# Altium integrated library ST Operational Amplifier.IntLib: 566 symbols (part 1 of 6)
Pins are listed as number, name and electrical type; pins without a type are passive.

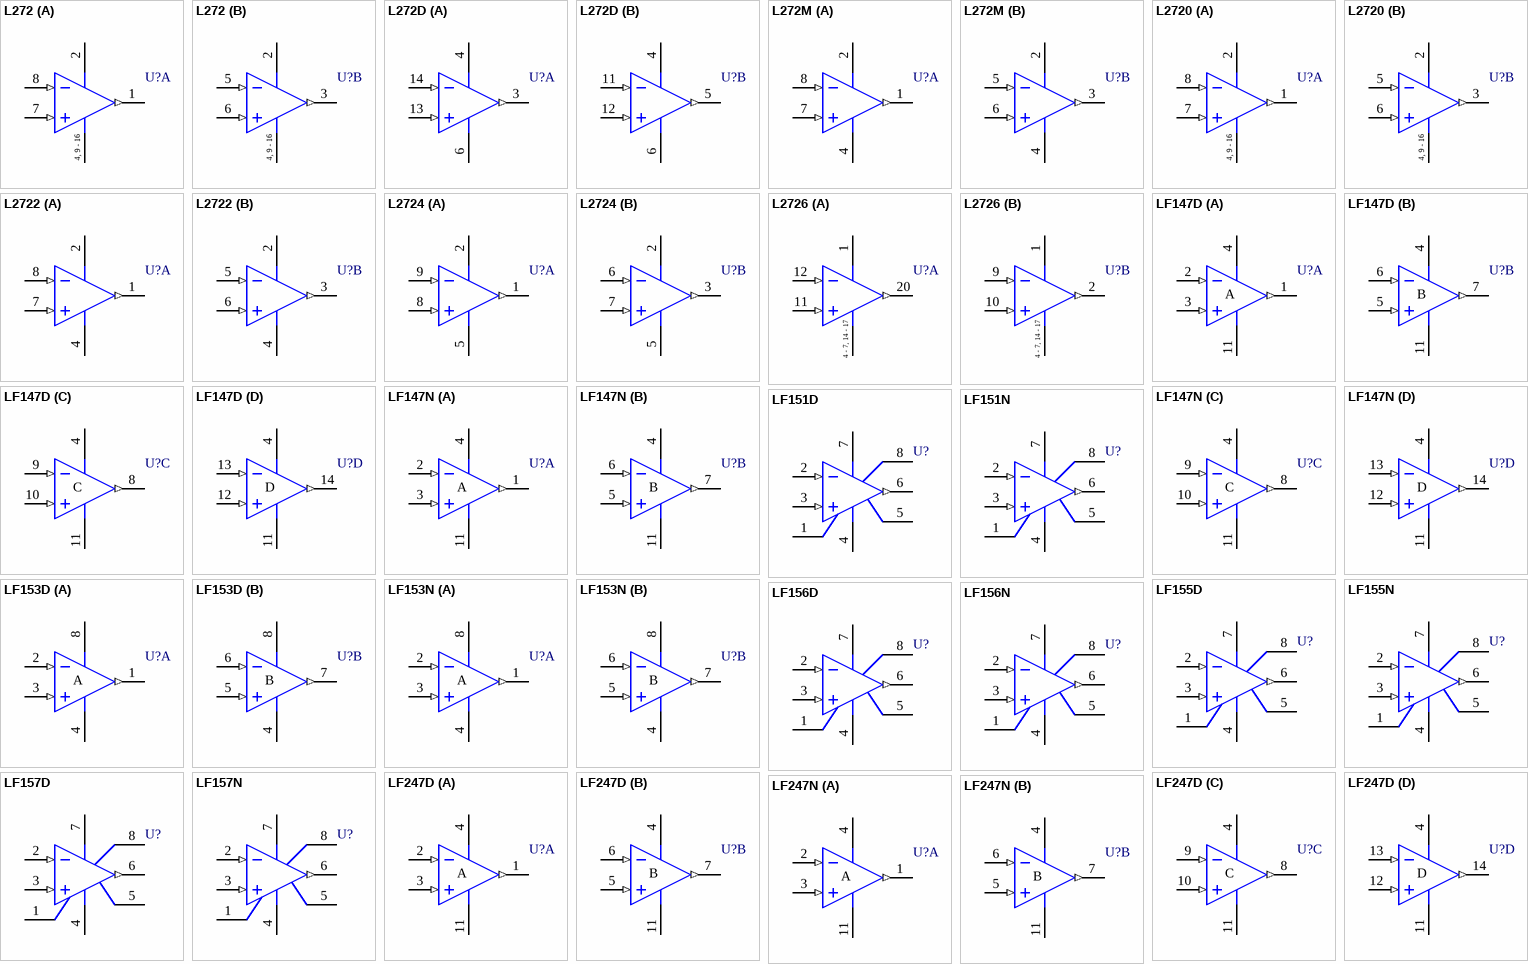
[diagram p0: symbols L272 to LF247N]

## L272
designator U?
Dual Power Operational Amplifier
footprint DIP16 (DIP; 16 Leads; Row Spacing 7.62 mm; Pitch 2.54 mm)
3D model DIP16 (DIP; 16 Leads; Row Spacing 7.62 mm; Pitch 2.54 mm)
pins on every part: 2 V+ (power), 4 V- (power), 9 V- (power), 10 V- (power), 11 V- (power), 12 V- (power), 13 V- (power), 14 V- (power), 15 V- (power), 16 V- (power)
part A pins: 1 OUT (out), 7 IN+ (in), 8 IN- (in)
part B pins: 3 OUT (out), 5 IN- (in), 6 IN+ (in)

## L272D
designator U?
Dual Power Operational Amplifier; Note: Pins 1, 2, 7, 8, 9, 10, 15 and 16 are NC and not drawn.
footprint SO16_N (SOIC, 16-Leads, Body 9.9x3.9mm, Pitch 1.27mm, IPC Medium Density)
footprint SO16_L (SOIC, 16-Leads, Body 9.9x3.9mm, Pitch 1.27mm, IPC High Density)
footprint SO16_M (SOIC, 16-Leads, Body 9.9x3.9mm, Pitch 1.27mm, IPC Low Density)
3D model SO16 (16-Pin Small Outline Integrated Circuit 1.27 mm Pitch)
pins on every part: 4 V+ (power), 6 V- (power)
part A pins: 3 OUT (out), 13 IN+ (in), 14 IN- (in)
part B pins: 5 OUT (out), 11 IN- (in), 12 IN+ (in)

## L272M
designator U?
Dual Power Operational Amplifier
footprint DIP8 (DIP; 8 Leads; Row Spacing 7.62 mm; Pitch 2.54 mm)
3D model DIP8 (DIP; 8 Leads; Row Spacing 7.62 mm; Pitch 2.54 mm)
pins on every part: 2 V+ (power), 4 V- (power)
part A pins: 1 OUT (out), 7 IN+ (in), 8 IN- (in)
part B pins: 3 OUT (out), 5 IN- (in), 6 IN+ (in)

## L2720
designator U?
Low-Drop Dual Power Operational Amplifier
footprint DIP16 (DIP; 16 Leads; Row Spacing 7.62 mm; Pitch 2.54 mm)
3D model DIP16 (DIP; 16 Leads; Row Spacing 7.62 mm; Pitch 2.54 mm)
pins on every part: 2 V+ (power), 4 V- (power), 9 V- (power), 10 V- (power), 11 V- (power), 12 V- (power), 13 V- (power), 14 V- (power), 15 V- (power), 16 V- (power)
part A pins: 1 OUT (out), 7 IN+ (in), 8 IN- (in)
part B pins: 3 OUT (out), 5 IN- (in), 6 IN+ (in)

## L2722
designator U?
Low-Drop Dual Power Operational Amplifier
footprint MDIP8 (DIP; 8 Leads; Row Spacing 7.62 mm; Pitch 2.54 mm)
pins on every part: 2 V+ (power), 4 V- (power)
part A pins: 1 OUT (out), 7 IN+ (in), 8 IN- (in)
part B pins: 3 OUT (out), 5 IN- (in), 6 IN+ (in)

## L2724
designator U?
Low-Drop Dual Power Operational Amplifier; Note: Pin number 4 is NC and not drawn.
footprint SIP9 (TO, Thru-Hole, Vertical, Heatsink Mounted; 9 In-Line Leads; Pitch 2.54 mm)
pins on every part: 2 V+ (power), 5 V- (power)
part A pins: 1 OUT (out), 8 IN+ (in), 9 IN- (in)
part B pins: 3 OUT (out), 6 IN- (in), 7 IN+ (in)

## L2726
designator U?
Low-Drop Dual Power Operational Amplifier; Note: Pins 3, 8, 13, 18  and 19 are NC and are not drawn.
footprint SO20_N (SOIC, 20-Leads, Body 12.8x7.5mm, Pitch 1.27mm, IPC Medium Density)
footprint SO20_L (SOIC, 20-Leads, Body 12.8x7.5mm, Pitch 1.27mm, IPC High Density)
footprint SO20_M (SOIC, 20-Leads, Body 12.8x7.5mm, Pitch 1.27mm, IPC Low Density)
3D model SO20 (20-Pin Plastic Small Outline Integrated Circuit 1.27 mm Pitch)
pins on every part: 1 V+ (power), 4 V- (power), 5 V- (power), 6 V- (power), 7 V- (power), 14 V- (power), 15 V- (power), 16 V- (power), 17 V- (power)
part A pins: 11 IN+ (in), 12 IN- (in), 20 OUT (out)
part B pins: 2 OUT (out), 9 IN- (in), 10 IN+ (in)

## LF147D
designator U?
Wide-Bandwidth Quad J-FET Operational Amplifier
footprint SO14_N (SOIC, 14-Leads, Body 8.7x3.9mm, Pitch 1.27mm, IPC Medium Density)
footprint SO14_L (SOIC, 14-Leads, Body 8.7x3.9mm, Pitch 1.27mm, IPC High Density)
footprint SO14_M (SOIC, 14-Leads, Body 8.7x3.9mm, Pitch 1.27mm, IPC Low Density)
3D model SO14 (14-Pin Small Outline Integrated Circuit 1.27 mm Pitch)
pins on every part: 4 V+ (power), 11 V- (power)
part A pins: 1 OUT (out), 2 IN- (in), 3 IN+ (in)
part B pins: 5 IN+ (in), 6 IN- (in), 7 OUT (out)
part C pins: 8 OUT (out), 9 IN- (in), 10 IN+ (in)
part D pins: 12 IN+ (in), 13 IN- (in), 14 OUT (out)

## LF147N
designator U?
Wide-Bandwidth Quad J-FET Operational Amplifier
footprint DIP14 (DIP; 14 Leads; Row Spacing 7.62 mm; Pitch 2.54 mm)
3D model DIP14 (DIP; 14 Leads; Row Spacing 7.62 mm; Pitch 2.54 mm)
pins on every part: 4 V+ (power), 11 V- (power)
part A pins: 1 OUT (out), 2 IN- (in), 3 IN+ (in)
part B pins: 5 IN+ (in), 6 IN- (in), 7 OUT (out)
part C pins: 8 OUT (out), 9 IN- (in), 10 IN+ (in)
part D pins: 12 IN+ (in), 13 IN- (in), 14 OUT (out)

## LF151D
designator U?
Wide-Bandwidth Single J-FET Operational Amplifier
footprint SO8_N (SOIC, 8-Leads, Body 4.9x3.9mm, Pitch 1.27mm, IPC Medium Density)
footprint SO8_L (SOIC, 8-Leads, Body 4.9x3.9mm, Pitch 1.27mm, IPC High Density)
footprint SO8_M (SOIC, 8-Leads, Body 4.9x3.9mm, Pitch 1.27mm, IPC Low Density)
3D model SO8 (8-Pin Small Outline Integrated Circuit 1.27 mm Pitch)
pins: 1 OS NULL, 2 IN- (in), 3 IN+ (in), 4 V- (power), 5 OS NULL, 6 OUT (out), 7 V+ (power), 8 NC

## LF151N
designator U?
Wide-Bandwidth Single J-FET Operational Amplifier
footprint DIP8 (DIP; 8 Leads; Row Spacing 7.62 mm; Pitch 2.54 mm)
3D model DIP8 (DIP; 8 Leads; Row Spacing 7.62 mm; Pitch 2.54 mm)
pins: 1 OS NULL, 2 IN- (in), 3 IN+ (in), 4 V- (power), 5 OS NULL, 6 OUT (out), 7 V+ (power), 8 NC

## LF153D
designator U?
Wide-Bandwidth Dual J-FET Operational Amplifier
footprint SO8_N (SOIC, 8-Leads, Body 4.9x3.9mm, Pitch 1.27mm, IPC Medium Density)
footprint SO8_L (SOIC, 8-Leads, Body 4.9x3.9mm, Pitch 1.27mm, IPC High Density)
footprint SO8_M (SOIC, 8-Leads, Body 4.9x3.9mm, Pitch 1.27mm, IPC Low Density)
3D model SO8 (8-Pin Small Outline Integrated Circuit 1.27 mm Pitch)
pins on every part: 4 V- (power), 8 V+ (power)
part A pins: 1 OUT (out), 2 IN- (in), 3 IN+ (in)
part B pins: 5 IN+ (in), 6 IN- (in), 7 OUT (out)

## LF153N
designator U?
Wide-Bandwidth Dual J-FET Operational Amplifier
footprint DIP8 (DIP; 8 Leads; Row Spacing 7.62 mm; Pitch 2.54 mm)
3D model DIP8 (DIP; 8 Leads; Row Spacing 7.62 mm; Pitch 2.54 mm)
pins on every part: 4 V- (power), 8 V+ (power)
part A pins: 1 OUT (out), 2 IN- (in), 3 IN+ (in)
part B pins: 5 IN+ (in), 6 IN- (in), 7 OUT (out)

## LF155D
designator U?
Wide-Bandwidth Single J-FET Operational Amplifier
footprint SOP8_N (SOIC, 8-Leads, Body 4.9x3.9mm, Pitch 1.27mm, IPC Medium Density)
footprint SOP8_L (SOIC, 8-Leads, Body 4.9x3.9mm, Pitch 1.27mm, IPC High Density)
footprint SOP8_M (SOIC, 8-Leads, Body 4.9x3.9mm, Pitch 1.27mm, IPC Low Density)
3D model SOP8 (8-Pin Small Outline Integrated Circuit 1.27 mm Pitch)
simulation model LF155 (SUBCKT)
pins: 1 OS NULL, 2 IN- (in), 3 IN+ (in), 4 V- (power), 5 OS NULL, 6 OUT (out), 7 V+ (power), 8 NC

## LF155N
designator U?
Wide-Bandwidth Single J-FET Operational Amplifier
footprint DIP8 (DIP; 8 Leads; Row Spacing 7.62 mm; Pitch 2.54 mm)
3D model DIP8 (DIP; 8 Leads; Row Spacing 7.62 mm; Pitch 2.54 mm)
simulation model LF155 (SUBCKT)
pins: 1 OS NULL, 2 IN- (in), 3 IN+ (in), 4 V- (power), 5 OS NULL, 6 OUT (out), 7 V+ (power), 8 NC

## LF156D
designator U?
Wide-Bandwidth Single J-FET Operational Amplifier
footprint SO8_N (SOIC, 8-Leads, Body 4.9x3.9mm, Pitch 1.27mm, IPC Medium Density)
footprint SO8_L (SOIC, 8-Leads, Body 4.9x3.9mm, Pitch 1.27mm, IPC High Density)
footprint SO8_M (SOIC, 8-Leads, Body 4.9x3.9mm, Pitch 1.27mm, IPC Low Density)
3D model SO8 (8-Pin Small Outline Integrated Circuit 1.27 mm Pitch)
simulation model LF156 (SUBCKT)
pins: 1 OS NULL, 2 IN- (in), 3 IN+ (in), 4 V- (power), 5 OS NULL, 6 OUT (out), 7 V+ (power), 8 NC

## LF156N
designator U?
Wide-Bandwidth Single J-FET Operational Amplifier
footprint DIP8 (DIP; 8 Leads; Row Spacing 7.62 mm; Pitch 2.54 mm)
3D model DIP8 (DIP; 8 Leads; Row Spacing 7.62 mm; Pitch 2.54 mm)
simulation model LF156 (SUBCKT)
pins: 1 OS NULL, 2 IN- (in), 3 IN+ (in), 4 V- (power), 5 OS NULL, 6 OUT (out), 7 V+ (power), 8 NC

## LF157D
designator U?
Wide-Bandwidth Single J-FET Operational Amplifier
footprint SO8_N (SOIC, 8-Leads, Body 4.9x3.9mm, Pitch 1.27mm, IPC Medium Density)
footprint SO8_L (SOIC, 8-Leads, Body 4.9x3.9mm, Pitch 1.27mm, IPC High Density)
footprint SO8_M (SOIC, 8-Leads, Body 4.9x3.9mm, Pitch 1.27mm, IPC Low Density)
3D model SO8 (8-Pin Small Outline Integrated Circuit 1.27 mm Pitch)
pins: 1 OS NULL, 2 IN- (in), 3 IN+ (in), 4 V- (power), 5 OS NULL, 6 OUT (out), 7 V+ (power), 8 NC

## LF157N
designator U?
Wide-Bandwidth Single J-FET Operational Amplifier
footprint DIP8 (DIP; 8 Leads; Row Spacing 7.62 mm; Pitch 2.54 mm)
3D model DIP8 (DIP; 8 Leads; Row Spacing 7.62 mm; Pitch 2.54 mm)
pins: 1 OS NULL, 2 IN- (in), 3 IN+ (in), 4 V- (power), 5 OS NULL, 6 OUT (out), 7 V+ (power), 8 NC

## LF247D
designator U?
Wide-Bandwidth Quad J-FET Operational Amplifier
footprint SO14_N (SOIC, 14-Leads, Body 8.7x3.9mm, Pitch 1.27mm, IPC Medium Density)
footprint SO14_L (SOIC, 14-Leads, Body 8.7x3.9mm, Pitch 1.27mm, IPC High Density)
footprint SO14_M (SOIC, 14-Leads, Body 8.7x3.9mm, Pitch 1.27mm, IPC Low Density)
3D model SO14 (14-Pin Small Outline Integrated Circuit 1.27 mm Pitch)
pins on every part: 4 V+ (power), 11 V- (power)
part A pins: 1 OUT (out), 2 IN- (in), 3 IN+ (in)
part B pins: 5 IN+ (in), 6 IN- (in), 7 OUT (out)
part C pins: 8 OUT (out), 9 IN- (in), 10 IN+ (in)
part D pins: 12 IN+ (in), 13 IN- (in), 14 OUT (out)

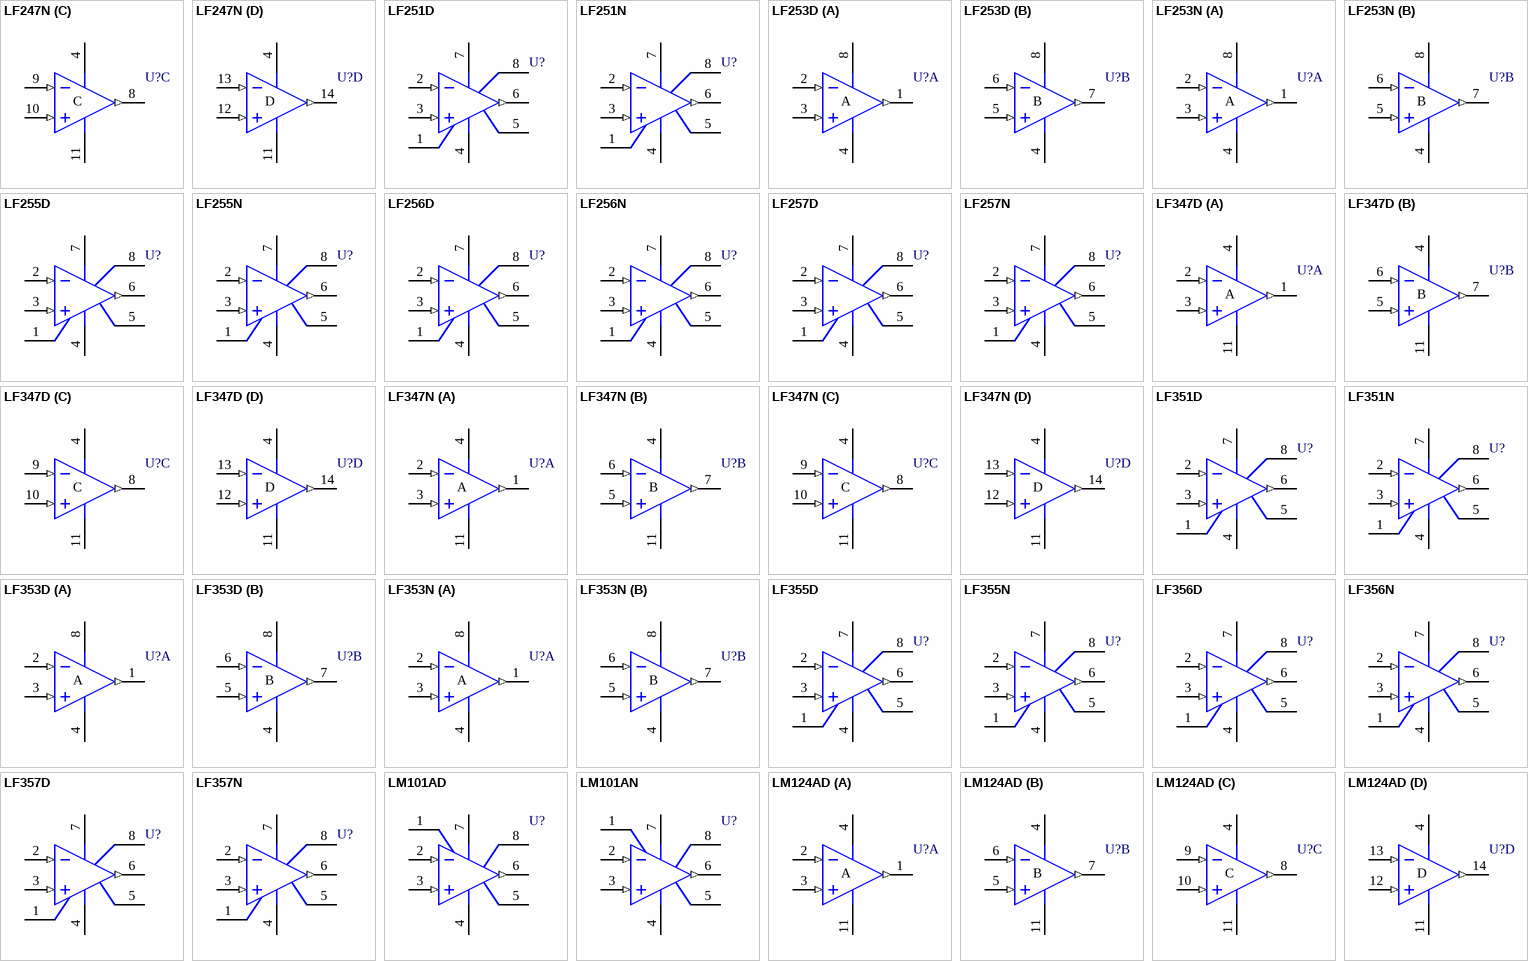
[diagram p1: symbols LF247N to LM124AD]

## LF247N
designator U?
Wide-Bandwidth Quad J-FET Operational Amplifier
footprint DIP14 (DIP; 14 Leads; Row Spacing 7.62 mm; Pitch 2.54 mm)
3D model DIP14 (DIP; 14 Leads; Row Spacing 7.62 mm; Pitch 2.54 mm)
pins on every part: 4 V+ (power), 11 V- (power)
part A pins: 1 OUT (out), 2 IN- (in), 3 IN+ (in)
part B pins: 5 IN+ (in), 6 IN- (in), 7 OUT (out)
part C pins: 8 OUT (out), 9 IN- (in), 10 IN+ (in)
part D pins: 12 IN+ (in), 13 IN- (in), 14 OUT (out)

## LF251D
designator U?
Wide-Bandwidth Single J-FET Operational Amplifier
footprint SO8_N (SOIC, 8-Leads, Body 4.9x3.9mm, Pitch 1.27mm, IPC Medium Density)
footprint SO8_L (SOIC, 8-Leads, Body 4.9x3.9mm, Pitch 1.27mm, IPC High Density)
footprint SO8_M (SOIC, 8-Leads, Body 4.9x3.9mm, Pitch 1.27mm, IPC Low Density)
3D model SO8 (8-Pin Small Outline Integrated Circuit 1.27 mm Pitch)
pins: 1 OS NULL, 2 IN- (in), 3 IN+ (in), 4 V- (power), 5 OS NULL, 6 OUT (out), 7 V+ (power), 8 NC

## LF251N
designator U?
Wide-Bandwidth Single J-FET Operational Amplifier
footprint DIP8 (DIP; 8 Leads; Row Spacing 7.62 mm; Pitch 2.54 mm)
3D model DIP8 (DIP; 8 Leads; Row Spacing 7.62 mm; Pitch 2.54 mm)
pins: 1 OS NULL, 2 IN- (in), 3 IN+ (in), 4 V- (power), 5 OS NULL, 6 OUT (out), 7 V+ (power), 8 NC

## LF253D
designator U?
Wide-Bandwidth Dual J-FET Operational Amplifier
footprint SO8_N (SOIC, 8-Leads, Body 4.9x3.9mm, Pitch 1.27mm, IPC Medium Density)
footprint SO8_L (SOIC, 8-Leads, Body 4.9x3.9mm, Pitch 1.27mm, IPC High Density)
footprint SO8_M (SOIC, 8-Leads, Body 4.9x3.9mm, Pitch 1.27mm, IPC Low Density)
3D model SO8 (8-Pin Small Outline Integrated Circuit 1.27 mm Pitch)
pins on every part: 4 V- (power), 8 V+ (power)
part A pins: 1 OUT (out), 2 IN- (in), 3 IN+ (in)
part B pins: 5 IN+ (in), 6 IN- (in), 7 OUT (out)

## LF253N
designator U?
Wide-Bandwidth Dual J-FET Operational Amplifier
footprint DIP8 (DIP; 8 Leads; Row Spacing 7.62 mm; Pitch 2.54 mm)
3D model DIP8 (DIP; 8 Leads; Row Spacing 7.62 mm; Pitch 2.54 mm)
pins on every part: 4 V- (power), 8 V+ (power)
part A pins: 1 OUT (out), 2 IN- (in), 3 IN+ (in)
part B pins: 5 IN+ (in), 6 IN- (in), 7 OUT (out)

## LF255D
designator U?
Wide-Bandwidth Single J-FET Operational Amplifier
footprint SO8_N (SOIC, 8-Leads, Body 4.9x3.9mm, Pitch 1.27mm, IPC Medium Density)
footprint SO8_L (SOIC, 8-Leads, Body 4.9x3.9mm, Pitch 1.27mm, IPC High Density)
footprint SO8_M (SOIC, 8-Leads, Body 4.9x3.9mm, Pitch 1.27mm, IPC Low Density)
3D model SO8 (8-Pin Small Outline Integrated Circuit 1.27 mm Pitch)
pins: 1 OS NULL, 2 IN- (in), 3 IN+ (in), 4 V- (power), 5 OS NULL, 6 OUT (out), 7 V+ (power), 8 NC

## LF255N
designator U?
Wide-Bandwidth Single J-FET Operational Amplifier
footprint DIP8 (DIP; 8 Leads; Row Spacing 7.62 mm; Pitch 2.54 mm)
3D model DIP8 (DIP; 8 Leads; Row Spacing 7.62 mm; Pitch 2.54 mm)
pins: 1 OS NULL, 2 IN- (in), 3 IN+ (in), 4 V- (power), 5 OS NULL, 6 OUT (out), 7 V+ (power), 8 NC

## LF256D
designator U?
Wide-Bandwidth Single J-FET Operational Amplifier
footprint SO8_N (SOIC, 8-Leads, Body 4.9x3.9mm, Pitch 1.27mm, IPC Medium Density)
footprint SO8_L (SOIC, 8-Leads, Body 4.9x3.9mm, Pitch 1.27mm, IPC High Density)
footprint SO8_M (SOIC, 8-Leads, Body 4.9x3.9mm, Pitch 1.27mm, IPC Low Density)
3D model SO8 (8-Pin Small Outline Integrated Circuit 1.27 mm Pitch)
pins: 1 OS NULL, 2 IN- (in), 3 IN+ (in), 4 V- (power), 5 OS NULL, 6 OUT (out), 7 V+ (power), 8 NC

## LF256N
designator U?
Wide-Bandwidth Single J-FET Operational Amplifier
footprint DIP8 (DIP; 8 Leads; Row Spacing 7.62 mm; Pitch 2.54 mm)
3D model DIP8 (DIP; 8 Leads; Row Spacing 7.62 mm; Pitch 2.54 mm)
pins: 1 OS NULL, 2 IN- (in), 3 IN+ (in), 4 V- (power), 5 OS NULL, 6 OUT (out), 7 V+ (power), 8 NC

## LF257D
designator U?
Wide-Bandwidth Single J-FET Operational Amplifier
footprint SO8_N (SOIC, 8-Leads, Body 4.9x3.9mm, Pitch 1.27mm, IPC Medium Density)
footprint SO8_L (SOIC, 8-Leads, Body 4.9x3.9mm, Pitch 1.27mm, IPC High Density)
footprint SO8_M (SOIC, 8-Leads, Body 4.9x3.9mm, Pitch 1.27mm, IPC Low Density)
3D model SO8 (8-Pin Small Outline Integrated Circuit 1.27 mm Pitch)
pins: 1 OS NULL, 2 IN- (in), 3 IN+ (in), 4 V- (power), 5 OS NULL, 6 OUT (out), 7 V+ (power), 8 NC

## LF257N
designator U?
Wide-Bandwidth Single J-FET Operational Amplifier
footprint DIP8 (DIP; 8 Leads; Row Spacing 7.62 mm; Pitch 2.54 mm)
3D model DIP8 (DIP; 8 Leads; Row Spacing 7.62 mm; Pitch 2.54 mm)
pins: 1 OS NULL, 2 IN- (in), 3 IN+ (in), 4 V- (power), 5 OS NULL, 6 OUT (out), 7 V+ (power), 8 NC

## LF347D
designator U?
Wide-Bandwidth Quad J-FET Operational Amplifier
footprint SO14_N (SOIC, 14-Leads, Body 8.7x3.9mm, Pitch 1.27mm, IPC Medium Density)
footprint SO14_L (SOIC, 14-Leads, Body 8.7x3.9mm, Pitch 1.27mm, IPC High Density)
footprint SO14_M (SOIC, 14-Leads, Body 8.7x3.9mm, Pitch 1.27mm, IPC Low Density)
3D model SO14 (14-Pin Small Outline Integrated Circuit 1.27 mm Pitch)
simulation model LF347 (SUBCKT)
pins on every part: 4 V+ (power), 11 V- (power)
part A pins: 1 OUT (out), 2 IN- (in), 3 IN+ (in)
part B pins: 5 IN+ (in), 6 IN- (in), 7 OUT (out)
part C pins: 8 OUT (out), 9 IN- (in), 10 IN+ (in)
part D pins: 12 IN+ (in), 13 IN- (in), 14 OUT (out)

## LF347N
designator U?
Wide-Bandwidth Quad J-FET Operational Amplifier
footprint DIP14 (DIP; 14 Leads; Row Spacing 7.62 mm; Pitch 2.54 mm)
3D model DIP14 (DIP; 14 Leads; Row Spacing 7.62 mm; Pitch 2.54 mm)
simulation model LF347 (SUBCKT)
pins on every part: 4 V+ (power), 11 V- (power)
part A pins: 1 OUT (out), 2 IN- (in), 3 IN+ (in)
part B pins: 5 IN+ (in), 6 IN- (in), 7 OUT (out)
part C pins: 8 OUT (out), 9 IN- (in), 10 IN+ (in)
part D pins: 12 IN+ (in), 13 IN- (in), 14 OUT (out)

## LF351D
designator U?
Wide-Bandwidth Single J-FET Operational Amplifier
footprint SO8_N (SOIC, 8-Leads, Body 4.9x3.9mm, Pitch 1.27mm, IPC Medium Density)
footprint SO8_L (SOIC, 8-Leads, Body 4.9x3.9mm, Pitch 1.27mm, IPC High Density)
footprint SO8_M (SOIC, 8-Leads, Body 4.9x3.9mm, Pitch 1.27mm, IPC Low Density)
3D model SO8 (8-Pin Small Outline Integrated Circuit 1.27 mm Pitch)
simulation model LF351 (SUBCKT)
pins: 1 OS NULL, 2 IN- (in), 3 IN+ (in), 4 V- (power), 5 OS NULL, 6 OUT (out), 7 V+ (power), 8 NC

## LF351N
designator U?
Wide-Bandwidth Single J-FET Operational Amplifier
footprint DIP8 (DIP; 8 Leads; Row Spacing 7.62 mm; Pitch 2.54 mm)
3D model DIP8 (DIP; 8 Leads; Row Spacing 7.62 mm; Pitch 2.54 mm)
simulation model LF351 (SUBCKT)
pins: 1 OS NULL, 2 IN- (in), 3 IN+ (in), 4 V- (power), 5 OS NULL, 6 OUT (out), 7 V+ (power), 8 NC

## LF353D
designator U?
Wide-Bandwidth Dual J-FET Operational Amplifier
footprint SO8_N (SOIC, 8-Leads, Body 4.9x3.9mm, Pitch 1.27mm, IPC Medium Density)
footprint SO8_L (SOIC, 8-Leads, Body 4.9x3.9mm, Pitch 1.27mm, IPC High Density)
footprint SO8_M (SOIC, 8-Leads, Body 4.9x3.9mm, Pitch 1.27mm, IPC Low Density)
3D model SO8 (8-Pin Small Outline Integrated Circuit 1.27 mm Pitch)
simulation model LF353D (SUBCKT)
pins on every part: 4 V- (power), 8 V+ (power)
part A pins: 1 OUT (out), 2 IN- (in), 3 IN+ (in)
part B pins: 5 IN+ (in), 6 IN- (in), 7 OUT (out)

## LF353N
designator U?
Wide-Bandwidth Dual J-FET Operational Amplifier
footprint DIP8 (DIP; 8 Leads; Row Spacing 7.62 mm; Pitch 2.54 mm)
3D model DIP8 (DIP; 8 Leads; Row Spacing 7.62 mm; Pitch 2.54 mm)
simulation model LF353N (SUBCKT)
pins on every part: 4 V- (power), 8 V+ (power)
part A pins: 1 OUT (out), 2 IN- (in), 3 IN+ (in)
part B pins: 5 IN+ (in), 6 IN- (in), 7 OUT (out)

## LF355D
designator U?
Wide-Bandwidth Single J-FET Operational Amplifier
footprint SO8_N (SOIC, 8-Leads, Body 4.9x3.9mm, Pitch 1.27mm, IPC Medium Density)
footprint SO8_L (SOIC, 8-Leads, Body 4.9x3.9mm, Pitch 1.27mm, IPC High Density)
footprint SO8_M (SOIC, 8-Leads, Body 4.9x3.9mm, Pitch 1.27mm, IPC Low Density)
3D model SO8 (8-Pin Small Outline Integrated Circuit 1.27 mm Pitch)
simulation model LF355 (SUBCKT)
pins: 1 OS NULL, 2 IN- (in), 3 IN+ (in), 4 V- (power), 5 OS NULL, 6 OUT (out), 7 V+ (power), 8 NC

## LF355N
designator U?
Wide-Bandwidth Single J-FET Operational Amplifier
footprint DIP8 (DIP; 8 Leads; Row Spacing 7.62 mm; Pitch 2.54 mm)
3D model DIP8 (DIP; 8 Leads; Row Spacing 7.62 mm; Pitch 2.54 mm)
simulation model LF355 (SUBCKT)
pins: 1 OS NULL, 2 IN- (in), 3 IN+ (in), 4 V- (power), 5 OS NULL, 6 OUT (out), 7 V+ (power), 8 NC

## LF356D
designator U?
Wide-Bandwidth Single J-FET Operational Amplifier
footprint SO8_N (SOIC, 8-Leads, Body 4.9x3.9mm, Pitch 1.27mm, IPC Medium Density)
footprint SO8_L (SOIC, 8-Leads, Body 4.9x3.9mm, Pitch 1.27mm, IPC High Density)
footprint SO8_M (SOIC, 8-Leads, Body 4.9x3.9mm, Pitch 1.27mm, IPC Low Density)
3D model SO8 (8-Pin Small Outline Integrated Circuit 1.27 mm Pitch)
simulation model LF356 (SUBCKT)
pins: 1 OS NULL, 2 IN- (in), 3 IN+ (in), 4 V- (power), 5 OS NULL, 6 OUT (out), 7 V+ (power), 8 NC

## LF356N
designator U?
Wide-Bandwidth Single J-FET Operational Amplifier
footprint DIP8 (DIP; 8 Leads; Row Spacing 7.62 mm; Pitch 2.54 mm)
3D model DIP8 (DIP; 8 Leads; Row Spacing 7.62 mm; Pitch 2.54 mm)
simulation model LF356 (SUBCKT)
pins: 1 OS NULL, 2 IN- (in), 3 IN+ (in), 4 V- (power), 5 OS NULL, 6 OUT (out), 7 V+ (power), 8 NC

## LF357D
designator U?
Wide-Bandwidth Single J-FET Operational Amplifier
footprint SO8_N (SOIC, 8-Leads, Body 4.9x3.9mm, Pitch 1.27mm, IPC Medium Density)
footprint SO8_L (SOIC, 8-Leads, Body 4.9x3.9mm, Pitch 1.27mm, IPC High Density)
footprint SO8_M (SOIC, 8-Leads, Body 4.9x3.9mm, Pitch 1.27mm, IPC Low Density)
3D model SO8 (8-Pin Small Outline Integrated Circuit 1.27 mm Pitch)
pins: 1 OS NULL, 2 IN- (in), 3 IN+ (in), 4 V- (power), 5 OS NULL, 6 OUT (out), 7 V+ (power), 8 NC

## LF357N
designator U?
Wide-Bandwidth Single J-FET Operational Amplifier
footprint DIP8 (DIP; 8 Leads; Row Spacing 7.62 mm; Pitch 2.54 mm)
3D model DIP8 (DIP; 8 Leads; Row Spacing 7.62 mm; Pitch 2.54 mm)
pins: 1 OS NULL, 2 IN- (in), 3 IN+ (in), 4 V- (power), 5 OS NULL, 6 OUT (out), 7 V+ (power), 8 NC

## LM101AD
designator U?
Single Operational Amplifier
footprint SO8_N (SOIC, 8-Leads, Body 4.9x3.9mm, Pitch 1.27mm, IPC Medium Density)
footprint SO8_L (SOIC, 8-Leads, Body 4.9x3.9mm, Pitch 1.27mm, IPC High Density)
footprint SO8_M (SOIC, 8-Leads, Body 4.9x3.9mm, Pitch 1.27mm, IPC Low Density)
3D model SO8 (8-Pin Small Outline Integrated Circuit 1.27 mm Pitch)
simulation model LM101A (SUBCKT)
pins: 1 BAL/CMPEN1, 2 IN- (in), 3 IN+ (in), 4 V- (power), 5 BAL, 6 OUT (out), 7 V+ (power), 8 CMPEN2

## LM101AN
designator U?
Single Operational Amplifier
footprint DIP8 (DIP; 8 Leads; Row Spacing 7.62 mm; Pitch 2.54 mm)
3D model DIP8 (DIP; 8 Leads; Row Spacing 7.62 mm; Pitch 2.54 mm)
simulation model LM101A (SUBCKT)
pins: 1 BAL/CMPEN1, 2 IN- (in), 3 IN+ (in), 4 V- (power), 5 BAL, 6 OUT (out), 7 V+ (power), 8 CMPEN2

## LM124AD
designator U?
Low-Power Quad Operational Amplifier
footprint SO14_N (SOIC, 14-Leads, Body 8.7x3.9mm, Pitch 1.27mm, IPC Medium Density)
footprint SO14_L (SOIC, 14-Leads, Body 8.7x3.9mm, Pitch 1.27mm, IPC High Density)
footprint SO14_M (SOIC, 14-Leads, Body 8.7x3.9mm, Pitch 1.27mm, IPC Low Density)
3D model SO14 (14-Pin Small Outline Integrated Circuit 1.27 mm Pitch)
pins on every part: 4 V+ (power), 11 V- (power)
part A pins: 1 OUT (out), 2 IN- (in), 3 IN+ (in)
part B pins: 5 IN+ (in), 6 IN- (in), 7 OUT (out)
part C pins: 8 OUT (out), 9 IN- (in), 10 IN+ (in)
part D pins: 12 IN+ (in), 13 IN- (in), 14 OUT (out)

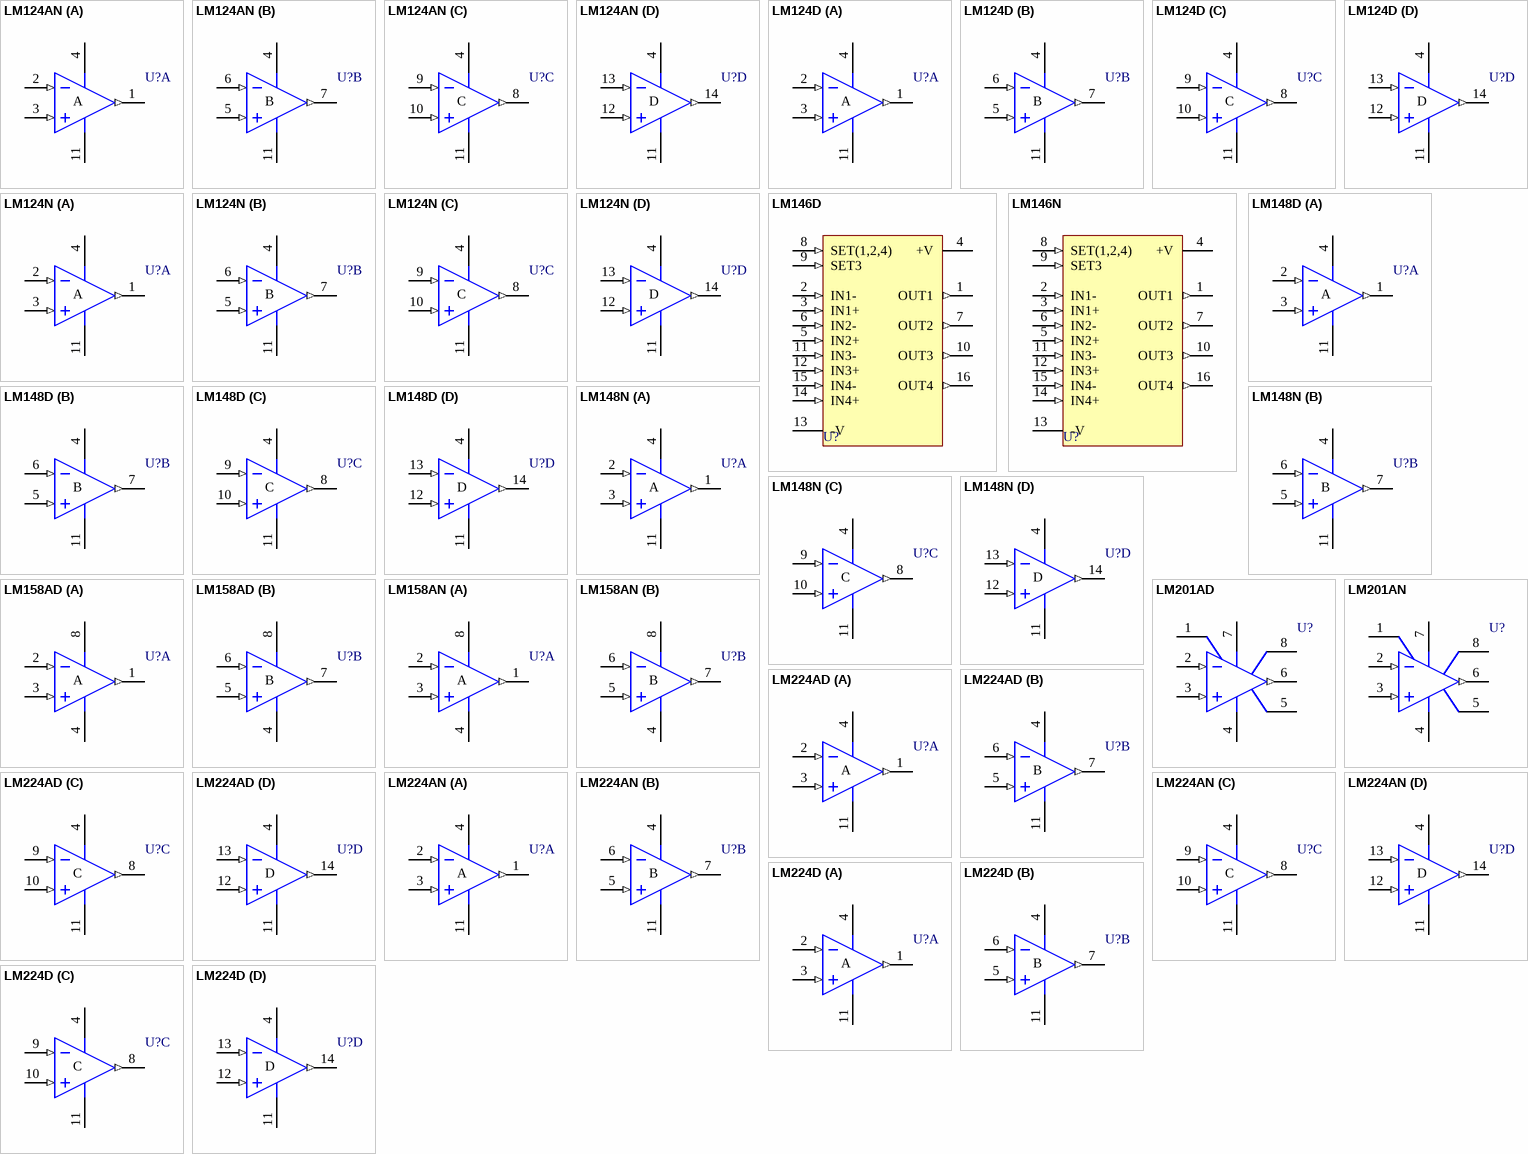
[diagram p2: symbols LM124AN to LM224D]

## LM124AN
designator U?
Low-Power Quad Operational Amplifier
footprint DIP14 (DIP; 14 Leads; Row Spacing 7.62 mm; Pitch 2.54 mm)
3D model DIP14 (DIP; 14 Leads; Row Spacing 7.62 mm; Pitch 2.54 mm)
pins on every part: 4 V+ (power), 11 V- (power)
part A pins: 1 OUT (out), 2 IN- (in), 3 IN+ (in)
part B pins: 5 IN+ (in), 6 IN- (in), 7 OUT (out)
part C pins: 8 OUT (out), 9 IN- (in), 10 IN+ (in)
part D pins: 12 IN+ (in), 13 IN- (in), 14 OUT (out)

## LM124D
designator U?
Low-Power Quad Operational Amplifier
footprint SO14_N (SOIC, 14-Leads, Body 8.7x3.9mm, Pitch 1.27mm, IPC Medium Density)
footprint SO14_L (SOIC, 14-Leads, Body 8.7x3.9mm, Pitch 1.27mm, IPC High Density)
footprint SO14_M (SOIC, 14-Leads, Body 8.7x3.9mm, Pitch 1.27mm, IPC Low Density)
3D model SO14 (14-Pin Small Outline Integrated Circuit 1.27 mm Pitch)
pins on every part: 4 V+ (power), 11 V- (power)
part A pins: 1 OUT (out), 2 IN- (in), 3 IN+ (in)
part B pins: 5 IN+ (in), 6 IN- (in), 7 OUT (out)
part C pins: 8 OUT (out), 9 IN- (in), 10 IN+ (in)
part D pins: 12 IN+ (in), 13 IN- (in), 14 OUT (out)

## LM124N
designator U?
Low-Power Quad Operational Amplifier
footprint DIP14 (DIP; 14 Leads; Row Spacing 7.62 mm; Pitch 2.54 mm)
3D model DIP14 (DIP; 14 Leads; Row Spacing 7.62 mm; Pitch 2.54 mm)
pins on every part: 4 V+ (power), 11 V- (power)
part A pins: 1 OUT (out), 2 IN- (in), 3 IN+ (in)
part B pins: 5 IN+ (in), 6 IN- (in), 7 OUT (out)
part C pins: 8 OUT (out), 9 IN- (in), 10 IN+ (in)
part D pins: 12 IN+ (in), 13 IN- (in), 14 OUT (out)

## LM146D
designator U?
Programmable Quad Bipolar Operational Amplifier
footprint SO16_N (SOIC, 16-Leads, Body 9.9x3.9mm, Pitch 1.27mm, IPC Medium Density)
footprint SO16_L (SOIC, 16-Leads, Body 9.9x3.9mm, Pitch 1.27mm, IPC High Density)
footprint SO16_M (SOIC, 16-Leads, Body 9.9x3.9mm, Pitch 1.27mm, IPC Low Density)
3D model SO16 (16-Pin Small Outline Integrated Circuit 1.27 mm Pitch)
pins: 1 OUT1 (out), 2 IN1- (in), 3 IN1+ (in), 4 +V (power), 5 IN2+ (in), 6 IN2- (in), 7 OUT2 (out), 8 SET(1,2,4) (in), 9 SET3 (in), 10 OUT3 (out), 11 IN3- (in), 12 IN3+ (in), 13 -V (power), 14 IN4+ (in), 15 IN4- (in), 16 OUT4 (out)

## LM146N
designator U?
Programmable Quad Bipolar Operational Amplifier
footprint DIP16 (DIP; 16 Leads; Row Spacing 7.62 mm; Pitch 2.54 mm)
3D model DIP16 (DIP; 16 Leads; Row Spacing 7.62 mm; Pitch 2.54 mm)
pins: 1 OUT1 (out), 2 IN1- (in), 3 IN1+ (in), 4 +V (power), 5 IN2+ (in), 6 IN2- (in), 7 OUT2 (out), 8 SET(1,2,4) (in), 9 SET3 (in), 10 OUT3 (out), 11 IN3- (in), 12 IN3+ (in), 13 -V (power), 14 IN4+ (in), 15 IN4- (in), 16 OUT4 (out)

## LM148D
designator U?
Four UA741 Quad Bipolar Operational Amplifier
footprint SO14_N (SOIC, 14-Leads, Body 8.7x3.9mm, Pitch 1.27mm, IPC Medium Density)
footprint SO14_L (SOIC, 14-Leads, Body 8.7x3.9mm, Pitch 1.27mm, IPC High Density)
footprint SO14_M (SOIC, 14-Leads, Body 8.7x3.9mm, Pitch 1.27mm, IPC Low Density)
3D model SO14 (14-Pin Small Outline Integrated Circuit 1.27 mm Pitch)
pins on every part: 4 V+ (power), 11 V- (power)
part A pins: 1 OUT (out), 2 IN- (in), 3 IN+ (in)
part B pins: 5 IN+ (in), 6 IN- (in), 7 OUT (out)
part C pins: 8 OUT (out), 9 IN- (in), 10 IN+ (in)
part D pins: 12 IN+ (in), 13 IN- (in), 14 OUT (out)

## LM148N
designator U?
Four UA741 Quad Bipolar Operational Amplifier
footprint DIP14 (DIP; 14 Leads; Row Spacing 7.62 mm; Pitch 2.54 mm)
3D model DIP14 (DIP; 14 Leads; Row Spacing 7.62 mm; Pitch 2.54 mm)
pins on every part: 4 V+ (power), 11 V- (power)
part A pins: 1 OUT (out), 2 IN- (in), 3 IN+ (in)
part B pins: 5 IN+ (in), 6 IN- (in), 7 OUT (out)
part C pins: 8 OUT (out), 9 IN- (in), 10 IN+ (in)
part D pins: 12 IN+ (in), 13 IN- (in), 14 OUT (out)

## LM158AD
designator U?
Low-Power Dual Operational Amplifier
footprint SO8_N (SOIC, 8-Leads, Body 4.9x3.9mm, Pitch 1.27mm, IPC Medium Density)
footprint SO8_L (SOIC, 8-Leads, Body 4.9x3.9mm, Pitch 1.27mm, IPC High Density)
footprint SO8_M (SOIC, 8-Leads, Body 4.9x3.9mm, Pitch 1.27mm, IPC Low Density)
3D model SO8 (8-Pin Small Outline Integrated Circuit 1.27 mm Pitch)
pins on every part: 4 V- (power), 8 V+ (power)
part A pins: 1 OUT (out), 2 IN- (in), 3 IN+ (in)
part B pins: 5 IN+ (in), 6 IN- (in), 7 OUT (out)

## LM158AN
designator U?
Low-Power Dual Operational Amplifier
footprint DIP8 (DIP; 8 Leads; Row Spacing 7.62 mm; Pitch 2.54 mm)
3D model DIP8 (DIP; 8 Leads; Row Spacing 7.62 mm; Pitch 2.54 mm)
pins on every part: 4 V- (power), 8 V+ (power)
part A pins: 1 OUT (out), 2 IN- (in), 3 IN+ (in)
part B pins: 5 IN+ (in), 6 IN- (in), 7 OUT (out)

## LM201AD
designator U?
Single Operational Amplifier
footprint SO8_N (SOIC, 8-Leads, Body 4.9x3.9mm, Pitch 1.27mm, IPC Medium Density)
footprint SO8_L (SOIC, 8-Leads, Body 4.9x3.9mm, Pitch 1.27mm, IPC High Density)
footprint SO8_M (SOIC, 8-Leads, Body 4.9x3.9mm, Pitch 1.27mm, IPC Low Density)
3D model SO8 (8-Pin Small Outline Integrated Circuit 1.27 mm Pitch)
pins: 1 BAL/CMPEN1, 2 IN- (in), 3 IN+ (in), 4 V- (power), 5 BAL, 6 OUT (out), 7 V+ (power), 8 CMPEN2

## LM201AN
designator U?
Single Operational Amplifier
footprint DIP8 (DIP; 8 Leads; Row Spacing 7.62 mm; Pitch 2.54 mm)
3D model DIP8 (DIP; 8 Leads; Row Spacing 7.62 mm; Pitch 2.54 mm)
pins: 1 BAL/CMPEN1, 2 IN- (in), 3 IN+ (in), 4 V- (power), 5 BAL, 6 OUT (out), 7 V+ (power), 8 CMPEN2

## LM224AD
designator U?
Low-Power Quad Operational Amplifier
footprint SO14_N (SOIC, 14-Leads, Body 8.7x3.9mm, Pitch 1.27mm, IPC Medium Density)
footprint SO14_L (SOIC, 14-Leads, Body 8.7x3.9mm, Pitch 1.27mm, IPC High Density)
footprint SO14_M (SOIC, 14-Leads, Body 8.7x3.9mm, Pitch 1.27mm, IPC Low Density)
3D model SO14 (14-Pin Small Outline Integrated Circuit 1.27 mm Pitch)
pins on every part: 4 V+ (power), 11 V- (power)
part A pins: 1 OUT (out), 2 IN- (in), 3 IN+ (in)
part B pins: 5 IN+ (in), 6 IN- (in), 7 OUT (out)
part C pins: 8 OUT (out), 9 IN- (in), 10 IN+ (in)
part D pins: 12 IN+ (in), 13 IN- (in), 14 OUT (out)

## LM224AN
designator U?
Low-Power Quad Operational Amplifier
footprint DIP14 (DIP; 14 Leads; Row Spacing 7.62 mm; Pitch 2.54 mm)
3D model DIP14 (DIP; 14 Leads; Row Spacing 7.62 mm; Pitch 2.54 mm)
pins on every part: 4 V+ (power), 11 V- (power)
part A pins: 1 OUT (out), 2 IN- (in), 3 IN+ (in)
part B pins: 5 IN+ (in), 6 IN- (in), 7 OUT (out)
part C pins: 8 OUT (out), 9 IN- (in), 10 IN+ (in)
part D pins: 12 IN+ (in), 13 IN- (in), 14 OUT (out)

## LM224D
designator U?
Low-Power Quad Operational Amplifier
footprint SO14_N (SOIC, 14-Leads, Body 8.7x3.9mm, Pitch 1.27mm, IPC Medium Density)
footprint SO14_L (SOIC, 14-Leads, Body 8.7x3.9mm, Pitch 1.27mm, IPC High Density)
footprint SO14_M (SOIC, 14-Leads, Body 8.7x3.9mm, Pitch 1.27mm, IPC Low Density)
3D model SO14 (14-Pin Small Outline Integrated Circuit 1.27 mm Pitch)
pins on every part: 4 V+ (power), 11 V- (power)
part A pins: 1 OUT (out), 2 IN- (in), 3 IN+ (in)
part B pins: 5 IN+ (in), 6 IN- (in), 7 OUT (out)
part C pins: 8 OUT (out), 9 IN- (in), 10 IN+ (in)
part D pins: 12 IN+ (in), 13 IN- (in), 14 OUT (out)

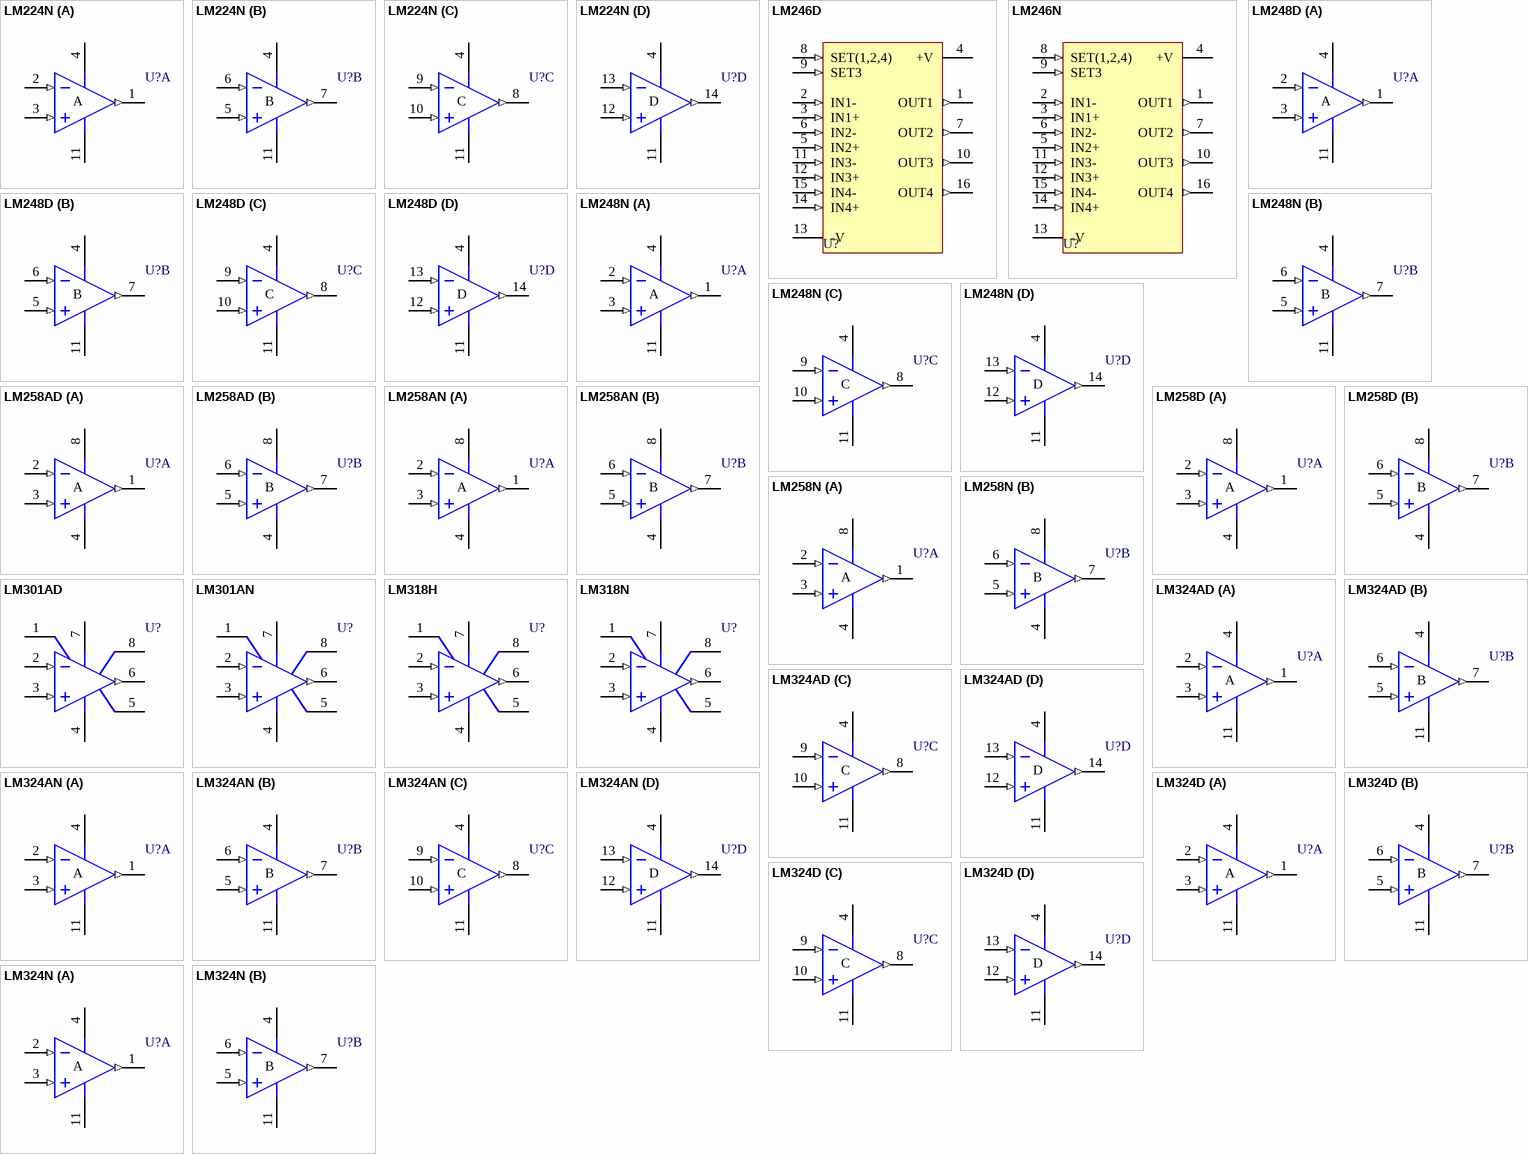
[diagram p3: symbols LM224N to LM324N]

## LM224N
designator U?
Low-Power Quad Operational Amplifier
footprint DIP14 (DIP; 14 Leads; Row Spacing 7.62 mm; Pitch 2.54 mm)
3D model DIP14 (DIP; 14 Leads; Row Spacing 7.62 mm; Pitch 2.54 mm)
pins on every part: 4 V+ (power), 11 V- (power)
part A pins: 1 OUT (out), 2 IN- (in), 3 IN+ (in)
part B pins: 5 IN+ (in), 6 IN- (in), 7 OUT (out)
part C pins: 8 OUT (out), 9 IN- (in), 10 IN+ (in)
part D pins: 12 IN+ (in), 13 IN- (in), 14 OUT (out)

## LM246D
designator U?
Programmable Quad Bipolar Operational Amplifier
footprint SO16_N (SOIC, 16-Leads, Body 9.9x3.9mm, Pitch 1.27mm, IPC Medium Density)
footprint SO16_L (SOIC, 16-Leads, Body 9.9x3.9mm, Pitch 1.27mm, IPC High Density)
footprint SO16_M (SOIC, 16-Leads, Body 9.9x3.9mm, Pitch 1.27mm, IPC Low Density)
3D model SO16 (16-Pin Small Outline Integrated Circuit 1.27 mm Pitch)
pins: 1 OUT1 (out), 2 IN1- (in), 3 IN1+ (in), 4 +V (power), 5 IN2+ (in), 6 IN2- (in), 7 OUT2 (out), 8 SET(1,2,4) (in), 9 SET3 (in), 10 OUT3 (out), 11 IN3- (in), 12 IN3+ (in), 13 -V (power), 14 IN4+ (in), 15 IN4- (in), 16 OUT4 (out)

## LM246N
designator U?
Programmable Quad Bipolar Operational Amplifier
footprint DIP16 (DIP; 16 Leads; Row Spacing 7.62 mm; Pitch 2.54 mm)
3D model DIP16 (DIP; 16 Leads; Row Spacing 7.62 mm; Pitch 2.54 mm)
pins: 1 OUT1 (out), 2 IN1- (in), 3 IN1+ (in), 4 +V (power), 5 IN2+ (in), 6 IN2- (in), 7 OUT2 (out), 8 SET(1,2,4) (in), 9 SET3 (in), 10 OUT3 (out), 11 IN3- (in), 12 IN3+ (in), 13 -V (power), 14 IN4+ (in), 15 IN4- (in), 16 OUT4 (out)

## LM248D
designator U?
Four UA741 Quad Bipolar Operational Amplifier
footprint SO14_N (SOIC, 14-Leads, Body 8.7x3.9mm, Pitch 1.27mm, IPC Medium Density)
footprint SO14_L (SOIC, 14-Leads, Body 8.7x3.9mm, Pitch 1.27mm, IPC High Density)
footprint SO14_M (SOIC, 14-Leads, Body 8.7x3.9mm, Pitch 1.27mm, IPC Low Density)
3D model SO14 (14-Pin Small Outline Integrated Circuit 1.27 mm Pitch)
pins on every part: 4 V+ (power), 11 V- (power)
part A pins: 1 OUT (out), 2 IN- (in), 3 IN+ (in)
part B pins: 5 IN+ (in), 6 IN- (in), 7 OUT (out)
part C pins: 8 OUT (out), 9 IN- (in), 10 IN+ (in)
part D pins: 12 IN+ (in), 13 IN- (in), 14 OUT (out)

## LM248N
designator U?
Four UA741 Quad Bipolar Operational Amplifier
footprint DIP14 (DIP; 14 Leads; Row Spacing 7.62 mm; Pitch 2.54 mm)
3D model DIP14 (DIP; 14 Leads; Row Spacing 7.62 mm; Pitch 2.54 mm)
pins on every part: 4 V+ (power), 11 V- (power)
part A pins: 1 OUT (out), 2 IN- (in), 3 IN+ (in)
part B pins: 5 IN+ (in), 6 IN- (in), 7 OUT (out)
part C pins: 8 OUT (out), 9 IN- (in), 10 IN+ (in)
part D pins: 12 IN+ (in), 13 IN- (in), 14 OUT (out)

## LM258AD
designator U?
Low-Power Dual Operational Amplifier
footprint SO8_N (SOIC, 8-Leads, Body 4.9x3.9mm, Pitch 1.27mm, IPC Medium Density)
footprint SO8_L (SOIC, 8-Leads, Body 4.9x3.9mm, Pitch 1.27mm, IPC High Density)
footprint SO8_M (SOIC, 8-Leads, Body 4.9x3.9mm, Pitch 1.27mm, IPC Low Density)
3D model SO8 (8-Pin Small Outline Integrated Circuit 1.27 mm Pitch)
pins on every part: 4 V- (power), 8 V+ (power)
part A pins: 1 OUT (out), 2 IN- (in), 3 IN+ (in)
part B pins: 5 IN+ (in), 6 IN- (in), 7 OUT (out)

## LM258AN
designator U?
Low-Power Dual Operational Amplifier
footprint DIP8 (DIP; 8 Leads; Row Spacing 7.62 mm; Pitch 2.54 mm)
3D model DIP8 (DIP; 8 Leads; Row Spacing 7.62 mm; Pitch 2.54 mm)
pins on every part: 4 V- (power), 8 V+ (power)
part A pins: 1 OUT (out), 2 IN- (in), 3 IN+ (in)
part B pins: 5 IN+ (in), 6 IN- (in), 7 OUT (out)

## LM258D
designator U?
Dual Low-Power Operational Amplifier
footprint SO8_N (SOIC, 8-Leads, Body 4.9x3.9mm, Pitch 1.27mm, IPC Medium Density)
footprint SO8_L (SOIC, 8-Leads, Body 4.9x3.9mm, Pitch 1.27mm, IPC High Density)
footprint SO8_M (SOIC, 8-Leads, Body 4.9x3.9mm, Pitch 1.27mm, IPC Low Density)
3D model SO8 (8-Pin Small Outline Integrated Circuit 1.27 mm Pitch)
pins on every part: 4 V- (power), 8 V+ (power)
part A pins: 1 OUT (out), 2 IN- (in), 3 IN+ (in)
part B pins: 5 IN+ (in), 6 IN- (in), 7 OUT (out)

## LM258N
designator U?
Dual Low-Power Operational Amplifier
footprint DIP8 (DIP; 8 Leads; Row Spacing 7.62 mm; Pitch 2.54 mm)
3D model DIP8 (DIP; 8 Leads; Row Spacing 7.62 mm; Pitch 2.54 mm)
pins on every part: 4 V- (power), 8 V+ (power)
part A pins: 1 OUT (out), 2 IN- (in), 3 IN+ (in)
part B pins: 5 IN+ (in), 6 IN- (in), 7 OUT (out)

## LM301AD
designator U?
Single Operational Amplifier
footprint SO8_N (SOIC, 8-Leads, Body 4.9x3.9mm, Pitch 1.27mm, IPC Medium Density)
footprint SO8_L (SOIC, 8-Leads, Body 4.9x3.9mm, Pitch 1.27mm, IPC High Density)
footprint SO8_M (SOIC, 8-Leads, Body 4.9x3.9mm, Pitch 1.27mm, IPC Low Density)
3D model SO8 (8-Pin Small Outline Integrated Circuit 1.27 mm Pitch)
simulation model LM301A (SUBCKT)
pins: 1 BAL/CMPEN1, 2 IN- (in), 3 IN+ (in), 4 V- (power), 5 BAL, 6 OUT (out), 7 V+ (power), 8 CMPEN2

## LM301AN
designator U?
Single Operational Amplifier
footprint DIP8 (DIP; 8 Leads; Row Spacing 7.62 mm; Pitch 2.54 mm)
3D model DIP8 (DIP; 8 Leads; Row Spacing 7.62 mm; Pitch 2.54 mm)
simulation model LM301A (SUBCKT)
pins: 1 BAL/CMPEN1, 2 IN- (in), 3 IN+ (in), 4 V- (power), 5 BAL, 6 OUT (out), 7 V+ (power), 8 CMPEN2

## LM318H
designator U?
Single Operational Amplifier
footprint TO99 (Can; 8 Leads; Pin Circle Dia. 5.08 mm; Lead Dia. 0.51 mm (max))
simulation model LM318 (SUBCKT)
pins: 1 BAL/CMPEN1, 2 IN- (in), 3 IN+ (in), 4 V- (power), 5 BAL/CMPEN3, 6 OUT (out), 7 V+ (power), 8 CMPEN2

## LM318N
designator U?
Single Operational Amplifier
footprint DIP8 (DIP; 8 Leads; Row Spacing 7.62 mm; Pitch 2.54 mm)
3D model DIP8 (DIP; 8 Leads; Row Spacing 7.62 mm; Pitch 2.54 mm)
simulation model LM318 (SUBCKT)
pins: 1 BAL/CMPEN1, 2 IN- (in), 3 IN+ (in), 4 V- (power), 5 BAL/CMPEN3, 6 OUT (out), 7 V+ (power), 8 CMPEN2

## LM324AD
designator U?
Low-Power Quad Operational Amplifier
footprint SO14_N (SOIC, 14-Leads, Body 8.7x3.9mm, Pitch 1.27mm, IPC Medium Density)
footprint SO14_L (SOIC, 14-Leads, Body 8.7x3.9mm, Pitch 1.27mm, IPC High Density)
footprint SO14_M (SOIC, 14-Leads, Body 8.7x3.9mm, Pitch 1.27mm, IPC Low Density)
3D model SO14 (14-Pin Small Outline Integrated Circuit 1.27 mm Pitch)
simulation model LM324 (SUBCKT)
pins on every part: 4 V+ (power), 11 V- (power)
part A pins: 1 OUT (out), 2 IN- (in), 3 IN+ (in)
part B pins: 5 IN+ (in), 6 IN- (in), 7 OUT (out)
part C pins: 8 OUT (out), 9 IN- (in), 10 IN+ (in)
part D pins: 12 IN+ (in), 13 IN- (in), 14 OUT (out)

## LM324AN
designator U?
Low-Power Quad Operational Amplifier
footprint DIP14 (DIP; 14 Leads; Row Spacing 7.62 mm; Pitch 2.54 mm)
3D model DIP14 (DIP; 14 Leads; Row Spacing 7.62 mm; Pitch 2.54 mm)
simulation model LM324 (SUBCKT)
pins on every part: 4 V+ (power), 11 V- (power)
part A pins: 1 OUT (out), 2 IN- (in), 3 IN+ (in)
part B pins: 5 IN+ (in), 6 IN- (in), 7 OUT (out)
part C pins: 8 OUT (out), 9 IN- (in), 10 IN+ (in)
part D pins: 12 IN+ (in), 13 IN- (in), 14 OUT (out)

## LM324D
designator U?
Low-Power Quad Operational Amplifier
footprint SO14_N (SOIC, 14-Leads, Body 8.7x3.9mm, Pitch 1.27mm, IPC Medium Density)
footprint SO14_L (SOIC, 14-Leads, Body 8.7x3.9mm, Pitch 1.27mm, IPC High Density)
footprint SO14_M (SOIC, 14-Leads, Body 8.7x3.9mm, Pitch 1.27mm, IPC Low Density)
3D model SO14 (14-Pin Small Outline Integrated Circuit 1.27 mm Pitch)
simulation model LM324 (SUBCKT)
pins on every part: 4 V+ (power), 11 V- (power)
part A pins: 1 OUT (out), 2 IN- (in), 3 IN+ (in)
part B pins: 5 IN+ (in), 6 IN- (in), 7 OUT (out)
part C pins: 8 OUT (out), 9 IN- (in), 10 IN+ (in)
part D pins: 12 IN+ (in), 13 IN- (in), 14 OUT (out)

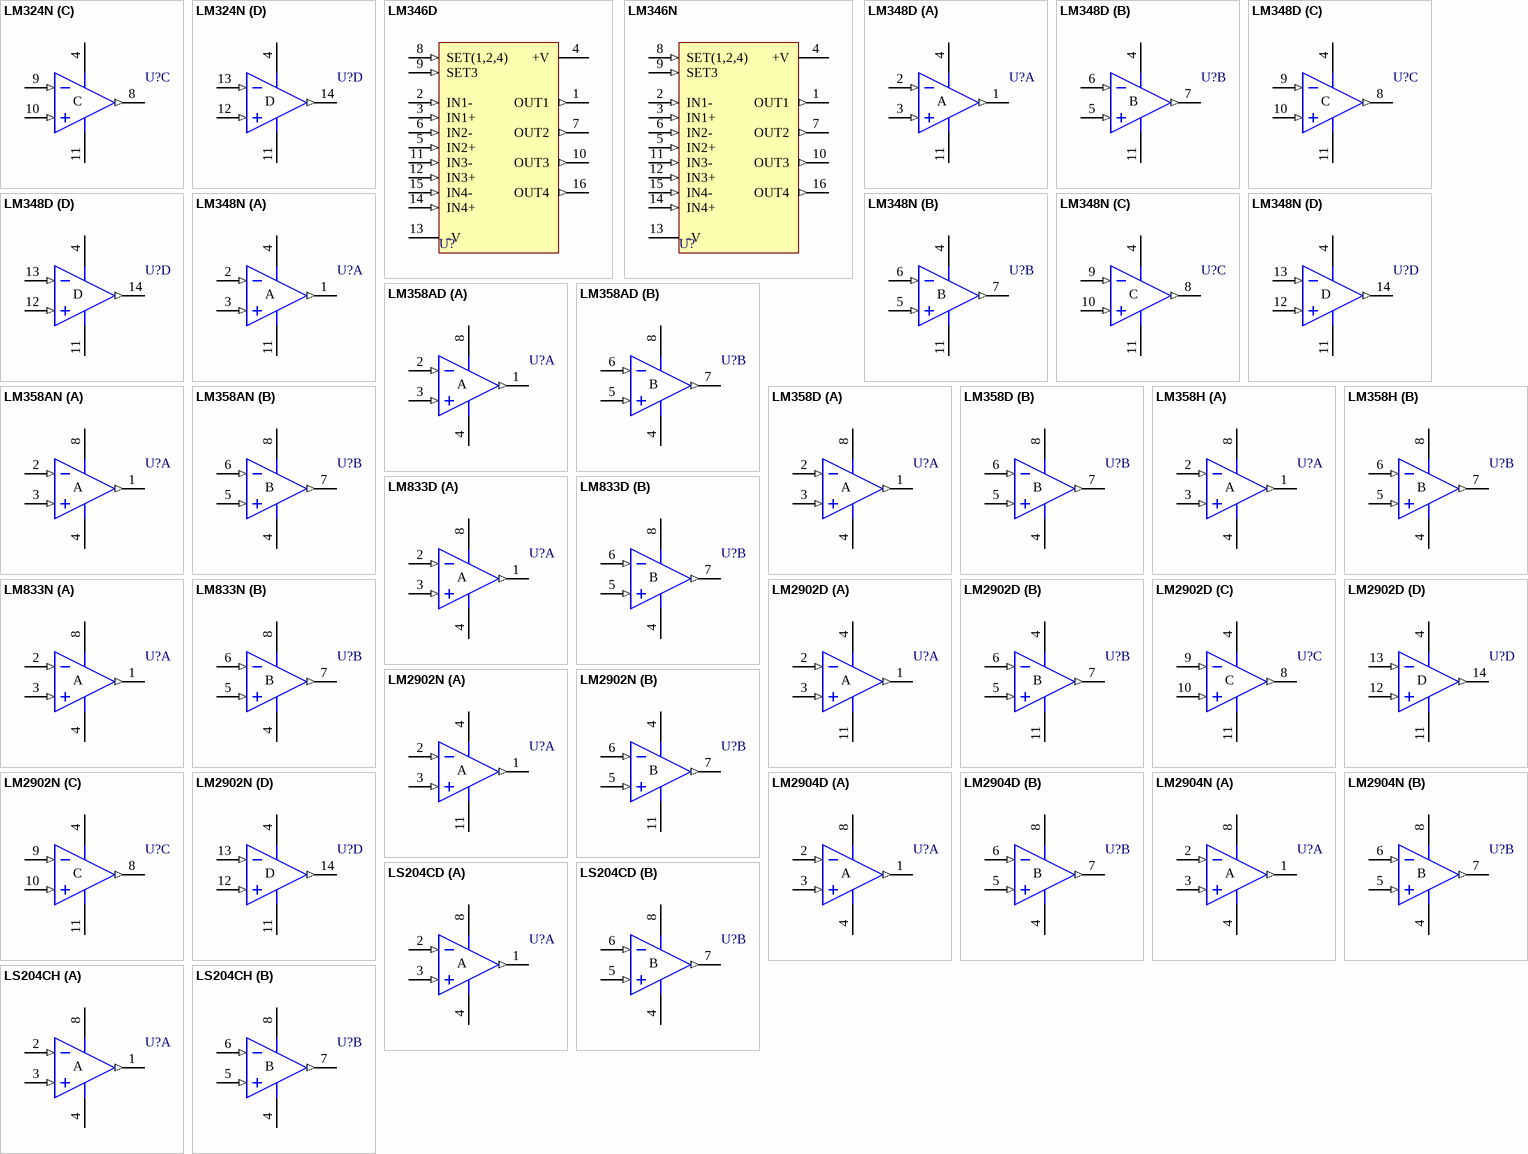
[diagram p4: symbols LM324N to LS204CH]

## LM324N
designator U?
Low-Power Quad Operational Amplifier
footprint DIP14 (DIP; 14 Leads; Row Spacing 7.62 mm; Pitch 2.54 mm)
3D model DIP14 (DIP; 14 Leads; Row Spacing 7.62 mm; Pitch 2.54 mm)
simulation model LM324 (SUBCKT)
pins on every part: 4 V+ (power), 11 V- (power)
part A pins: 1 OUT (out), 2 IN- (in), 3 IN+ (in)
part B pins: 5 IN+ (in), 6 IN- (in), 7 OUT (out)
part C pins: 8 OUT (out), 9 IN- (in), 10 IN+ (in)
part D pins: 12 IN+ (in), 13 IN- (in), 14 OUT (out)

## LM346D
designator U?
Programmable Quad Bipolar Operational Amplifier
footprint SO16_N (SOIC, 16-Leads, Body 9.9x3.9mm, Pitch 1.27mm, IPC Medium Density)
footprint SO16_L (SOIC, 16-Leads, Body 9.9x3.9mm, Pitch 1.27mm, IPC High Density)
footprint SO16_M (SOIC, 16-Leads, Body 9.9x3.9mm, Pitch 1.27mm, IPC Low Density)
3D model SO16 (16-Pin Small Outline Integrated Circuit 1.27 mm Pitch)
pins: 1 OUT1 (out), 2 IN1- (in), 3 IN1+ (in), 4 +V (power), 5 IN2+ (in), 6 IN2- (in), 7 OUT2 (out), 8 SET(1,2,4) (in), 9 SET3 (in), 10 OUT3 (out), 11 IN3- (in), 12 IN3+ (in), 13 -V (power), 14 IN4+ (in), 15 IN4- (in), 16 OUT4 (out)

## LM346N
designator U?
Programmable Quad Bipolar Operational Amplifier
footprint DIP16 (DIP; 16 Leads; Row Spacing 7.62 mm; Pitch 2.54 mm)
3D model DIP16 (DIP; 16 Leads; Row Spacing 7.62 mm; Pitch 2.54 mm)
pins: 1 OUT1 (out), 2 IN1- (in), 3 IN1+ (in), 4 +V (power), 5 IN2+ (in), 6 IN2- (in), 7 OUT2 (out), 8 SET(1,2,4) (in), 9 SET3 (in), 10 OUT3 (out), 11 IN3- (in), 12 IN3+ (in), 13 -V (power), 14 IN4+ (in), 15 IN4- (in), 16 OUT4 (out)

## LM348D
designator U?
Four UA741 Quad Bipolar Operational Amplifier
footprint SO14_N (SOIC, 14-Leads, Body 8.7x3.9mm, Pitch 1.27mm, IPC Medium Density)
footprint SO14_L (SOIC, 14-Leads, Body 8.7x3.9mm, Pitch 1.27mm, IPC High Density)
footprint SO14_M (SOIC, 14-Leads, Body 8.7x3.9mm, Pitch 1.27mm, IPC Low Density)
3D model SO14 (14-Pin Small Outline Integrated Circuit 1.27 mm Pitch)
simulation model LM348 (SUBCKT)
pins on every part: 4 V+ (power), 11 V- (power)
part A pins: 1 OUT (out), 2 IN- (in), 3 IN+ (in)
part B pins: 5 IN+ (in), 6 IN- (in), 7 OUT (out)
part C pins: 8 OUT (out), 9 IN- (in), 10 IN+ (in)
part D pins: 12 IN+ (in), 13 IN- (in), 14 OUT (out)

## LM348N
designator U?
Four UA741 Quad Bipolar Operational Amplifier
footprint DIP14 (DIP; 14 Leads; Row Spacing 7.62 mm; Pitch 2.54 mm)
3D model DIP14 (DIP; 14 Leads; Row Spacing 7.62 mm; Pitch 2.54 mm)
simulation model LM348 (SUBCKT)
pins on every part: 4 V+ (power), 11 V- (power)
part A pins: 1 OUT (out), 2 IN- (in), 3 IN+ (in)
part B pins: 5 IN+ (in), 6 IN- (in), 7 OUT (out)
part C pins: 8 OUT (out), 9 IN- (in), 10 IN+ (in)
part D pins: 12 IN+ (in), 13 IN- (in), 14 OUT (out)

## LM358AD
designator U?
Low-Power Dual Operational Amplifier
footprint SO8_N (SOIC, 8-Leads, Body 4.9x3.9mm, Pitch 1.27mm, IPC Medium Density)
footprint SO8_L (SOIC, 8-Leads, Body 4.9x3.9mm, Pitch 1.27mm, IPC High Density)
footprint SO8_M (SOIC, 8-Leads, Body 4.9x3.9mm, Pitch 1.27mm, IPC Low Density)
3D model SO8 (8-Pin Small Outline Integrated Circuit 1.27 mm Pitch)
simulation model LM358 (SUBCKT)
pins on every part: 4 V- (power), 8 V+ (power)
part A pins: 1 OUT (out), 2 IN- (in), 3 IN+ (in)
part B pins: 5 IN+ (in), 6 IN- (in), 7 OUT (out)

## LM358AN
designator U?
Low-Power Dual Operational Amplifier
footprint DIP8 (DIP; 8 Leads; Row Spacing 7.62 mm; Pitch 2.54 mm)
3D model DIP8 (DIP; 8 Leads; Row Spacing 7.62 mm; Pitch 2.54 mm)
simulation model LM358 (SUBCKT)
pins on every part: 4 V- (power), 8 V+ (power)
part A pins: 1 OUT (out), 2 IN- (in), 3 IN+ (in)
part B pins: 5 IN+ (in), 6 IN- (in), 7 OUT (out)

## LM358D
designator U?
Dual Low-Power Operational Amplifier
footprint SO8_N (SOIC, 8-Leads, Body 4.9x3.9mm, Pitch 1.27mm, IPC Medium Density)
footprint SO8_L (SOIC, 8-Leads, Body 4.9x3.9mm, Pitch 1.27mm, IPC High Density)
footprint SO8_M (SOIC, 8-Leads, Body 4.9x3.9mm, Pitch 1.27mm, IPC Low Density)
3D model SO8 (8-Pin Small Outline Integrated Circuit 1.27 mm Pitch)
simulation model LM358 (SUBCKT)
pins on every part: 4 V- (power), 8 V+ (power)
part A pins: 1 OUT (out), 2 IN- (in), 3 IN+ (in)
part B pins: 5 IN+ (in), 6 IN- (in), 7 OUT (out)

## LM358H
designator U?
Dual Low-Power Operational Amplifier
footprint DIP8 (DIP; 8 Leads; Row Spacing 7.62 mm; Pitch 2.54 mm)
3D model DIP8 (DIP; 8 Leads; Row Spacing 7.62 mm; Pitch 2.54 mm)
simulation model LM358 (SUBCKT)
pins on every part: 4 V- (power), 8 V+ (power)
part A pins: 1 OUT (out), 2 IN- (in), 3 IN+ (in)
part B pins: 5 IN+ (in), 6 IN- (in), 7 OUT (out)

## LM833D
designator U?
Low-Noise Dual Operational Amplifier
footprint SO8_N (SOIC, 8-Leads, Body 4.9x3.9mm, Pitch 1.27mm, IPC Medium Density)
footprint SO8_L (SOIC, 8-Leads, Body 4.9x3.9mm, Pitch 1.27mm, IPC High Density)
footprint SO8_M (SOIC, 8-Leads, Body 4.9x3.9mm, Pitch 1.27mm, IPC Low Density)
3D model SO8 (8-Pin Small Outline Integrated Circuit 1.27 mm Pitch)
simulation model LM833 (SUBCKT)
pins on every part: 4 V- (power), 8 V+ (power)
part A pins: 1 OUT (out), 2 IN- (in), 3 IN+ (in)
part B pins: 5 IN+ (in), 6 IN- (in), 7 OUT (out)

## LM833N
designator U?
Low-Noise Dual Operational Amplifier
footprint DIP8 (DIP; 8 Leads; Row Spacing 7.62 mm; Pitch 2.54 mm)
3D model DIP8 (DIP; 8 Leads; Row Spacing 7.62 mm; Pitch 2.54 mm)
simulation model LM833 (SUBCKT)
pins on every part: 4 V- (power), 8 V+ (power)
part A pins: 1 OUT (out), 2 IN- (in), 3 IN+ (in)
part B pins: 5 IN+ (in), 6 IN- (in), 7 OUT (out)

## LM2902D
designator U?
Low-Power Quad Operational Amplifier
footprint SO14_N (SOIC, 14-Leads, Body 8.7x3.9mm, Pitch 1.27mm, IPC Medium Density)
footprint SO14_L (SOIC, 14-Leads, Body 8.7x3.9mm, Pitch 1.27mm, IPC High Density)
footprint SO14_M (SOIC, 14-Leads, Body 8.7x3.9mm, Pitch 1.27mm, IPC Low Density)
3D model SO14 (14-Pin Small Outline Integrated Circuit 1.27 mm Pitch)
simulation model LM2902 (SUBCKT)
pins on every part: 4 V+ (power), 11 V- (power)
part A pins: 1 OUT (out), 2 IN- (in), 3 IN+ (in)
part B pins: 5 IN+ (in), 6 IN- (in), 7 OUT (out)
part C pins: 8 OUT (out), 9 IN- (in), 10 IN+ (in)
part D pins: 12 IN+ (in), 13 IN- (in), 14 OUT (out)

## LM2902N
designator U?
Low-Power Quad Operational Amplifier
footprint DIP14 (DIP; 14 Leads; Row Spacing 7.62 mm; Pitch 2.54 mm)
3D model DIP14 (DIP; 14 Leads; Row Spacing 7.62 mm; Pitch 2.54 mm)
simulation model LM2902 (SUBCKT)
pins on every part: 4 V+ (power), 11 V- (power)
part A pins: 1 OUT (out), 2 IN- (in), 3 IN+ (in)
part B pins: 5 IN+ (in), 6 IN- (in), 7 OUT (out)
part C pins: 8 OUT (out), 9 IN- (in), 10 IN+ (in)
part D pins: 12 IN+ (in), 13 IN- (in), 14 OUT (out)

## LM2904D
designator U?
Low-Power Dual Operational Amplifier
footprint SO8_N (SOIC, 8-Leads, Body 4.9x3.9mm, Pitch 1.27mm, IPC Medium Density)
footprint SO8_L (SOIC, 8-Leads, Body 4.9x3.9mm, Pitch 1.27mm, IPC High Density)
footprint SO8_M (SOIC, 8-Leads, Body 4.9x3.9mm, Pitch 1.27mm, IPC Low Density)
3D model SO8 (8-Pin Small Outline Integrated Circuit 1.27 mm Pitch)
simulation model LM2904 (SUBCKT)
pins on every part: 4 V- (power), 8 V+ (power)
part A pins: 1 OUT (out), 2 IN- (in), 3 IN+ (in)
part B pins: 5 IN+ (in), 6 IN- (in), 7 OUT (out)

## LM2904N
designator U?
Low-Power Dual Operational Amplifier
footprint DIP8 (DIP; 8 Leads; Row Spacing 7.62 mm; Pitch 2.54 mm)
3D model DIP8 (DIP; 8 Leads; Row Spacing 7.62 mm; Pitch 2.54 mm)
simulation model LM2904 (SUBCKT)
pins on every part: 4 V- (power), 8 V+ (power)
part A pins: 1 OUT (out), 2 IN- (in), 3 IN+ (in)
part B pins: 5 IN+ (in), 6 IN- (in), 7 OUT (out)

## LS204CD
designator U?
High-Performance Dual Operational Amplifier
footprint SO8_N (SOIC, 8-Leads, Body 4.9x3.9mm, Pitch 1.27mm, IPC Medium Density)
footprint SO8_L (SOIC, 8-Leads, Body 4.9x3.9mm, Pitch 1.27mm, IPC High Density)
footprint SO8_M (SOIC, 8-Leads, Body 4.9x3.9mm, Pitch 1.27mm, IPC Low Density)
3D model SO8 (8-Pin Small Outline Integrated Circuit 1.27 mm Pitch)
pins on every part: 4 V- (power), 8 V+ (power)
part A pins: 1 OUT (out), 2 IN- (in), 3 IN+ (in)
part B pins: 5 IN+ (in), 6 IN- (in), 7 OUT (out)

## LS204CH
designator U?
High-Performance Dual Operational Amplifier
footprint TO99 (Can; 8 Leads; Pin Circle Dia. 5.08 mm; Lead Dia. 0.51 mm (max))
pins on every part: 4 V- (power), 8 V+ (power)
part A pins: 1 OUT (out), 2 IN- (in), 3 IN+ (in)
part B pins: 5 IN+ (in), 6 IN- (in), 7 OUT (out)

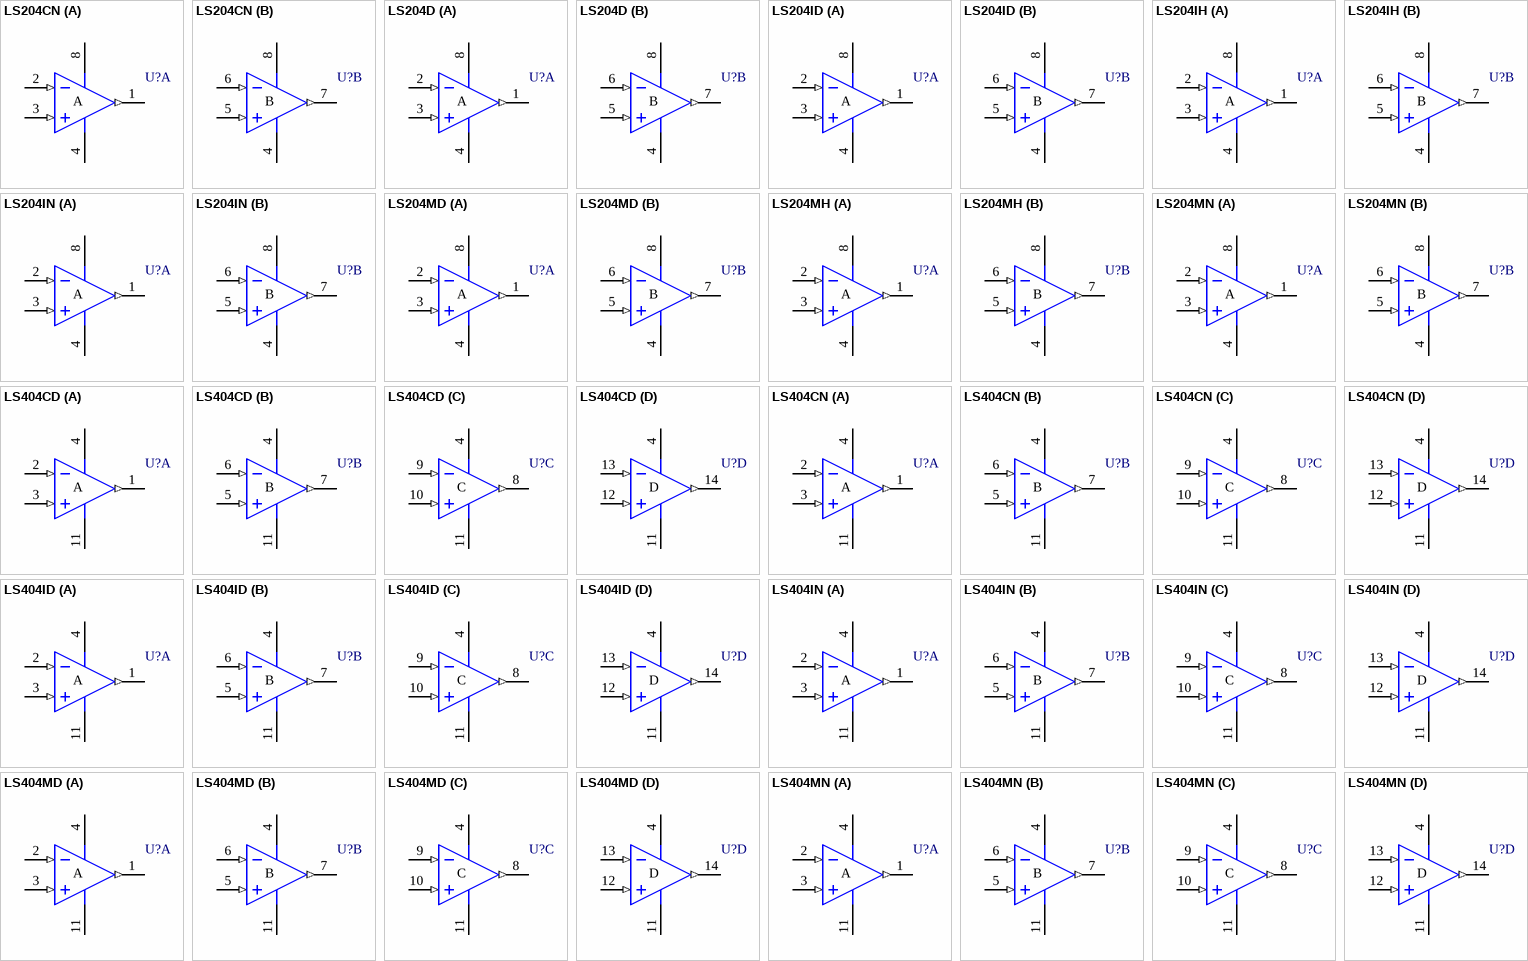
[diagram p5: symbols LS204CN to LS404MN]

## LS204CN
designator U?
High-Performance Dual Operational Amplifier
footprint DIP8 (DIP; 8 Leads; Row Spacing 7.62 mm; Pitch 2.54 mm)
3D model DIP8 (DIP; 8 Leads; Row Spacing 7.62 mm; Pitch 2.54 mm)
pins on every part: 4 V- (power), 8 V+ (power)
part A pins: 1 OUT (out), 2 IN- (in), 3 IN+ (in)
part B pins: 5 IN+ (in), 6 IN- (in), 7 OUT (out)

## LS204D
designator U?
High-Performance Dual Operational Amplifier
footprint SO8_N (SOIC, 8-Leads, Body 4.9x3.9mm, Pitch 1.27mm, IPC Medium Density)
footprint SO8_L (SOIC, 8-Leads, Body 4.9x3.9mm, Pitch 1.27mm, IPC High Density)
footprint SO8_M (SOIC, 8-Leads, Body 4.9x3.9mm, Pitch 1.27mm, IPC Low Density)
3D model SO8 (8-Pin Small Outline Integrated Circuit 1.27 mm Pitch)
pins on every part: 4 V- (power), 8 V+ (power)
part A pins: 1 OUT (out), 2 IN- (in), 3 IN+ (in)
part B pins: 5 IN+ (in), 6 IN- (in), 7 OUT (out)

## LS204ID
designator U?
High-Performance Dual Operational Amplifier
footprint SO8_N (SOIC, 8-Leads, Body 4.9x3.9mm, Pitch 1.27mm, IPC Medium Density)
footprint SO8_L (SOIC, 8-Leads, Body 4.9x3.9mm, Pitch 1.27mm, IPC High Density)
footprint SO8_M (SOIC, 8-Leads, Body 4.9x3.9mm, Pitch 1.27mm, IPC Low Density)
3D model SO8 (8-Pin Small Outline Integrated Circuit 1.27 mm Pitch)
pins on every part: 4 V- (power), 8 V+ (power)
part A pins: 1 OUT (out), 2 IN- (in), 3 IN+ (in)
part B pins: 5 IN+ (in), 6 IN- (in), 7 OUT (out)

## LS204IH
designator U?
High-Performance Dual Operational Amplifier
footprint TO99 (Can; 8 Leads; Pin Circle Dia. 5.08 mm; Lead Dia. 0.51 mm (max))
pins on every part: 4 V- (power), 8 V+ (power)
part A pins: 1 OUT (out), 2 IN- (in), 3 IN+ (in)
part B pins: 5 IN+ (in), 6 IN- (in), 7 OUT (out)

## LS204IN
designator U?
High-Performance Dual Operational Amplifier
footprint DIP8 (DIP; 8 Leads; Row Spacing 7.62 mm; Pitch 2.54 mm)
3D model DIP8 (DIP; 8 Leads; Row Spacing 7.62 mm; Pitch 2.54 mm)
pins on every part: 4 V- (power), 8 V+ (power)
part A pins: 1 OUT (out), 2 IN- (in), 3 IN+ (in)
part B pins: 5 IN+ (in), 6 IN- (in), 7 OUT (out)

## LS204MD
designator U?
High-Performance Dual Operational Amplifier
footprint SO8_N (SOIC, 8-Leads, Body 4.9x3.9mm, Pitch 1.27mm, IPC Medium Density)
footprint SO8_L (SOIC, 8-Leads, Body 4.9x3.9mm, Pitch 1.27mm, IPC High Density)
footprint SO8_M (SOIC, 8-Leads, Body 4.9x3.9mm, Pitch 1.27mm, IPC Low Density)
3D model SO8 (8-Pin Small Outline Integrated Circuit 1.27 mm Pitch)
pins on every part: 4 V- (power), 8 V+ (power)
part A pins: 1 OUT (out), 2 IN- (in), 3 IN+ (in)
part B pins: 5 IN+ (in), 6 IN- (in), 7 OUT (out)

## LS204MH
designator U?
High-Performance Dual Operational Amplifier
footprint TO99 (Can; 8 Leads; Pin Circle Dia. 5.08 mm; Lead Dia. 0.51 mm (max))
pins on every part: 4 V- (power), 8 V+ (power)
part A pins: 1 OUT (out), 2 IN- (in), 3 IN+ (in)
part B pins: 5 IN+ (in), 6 IN- (in), 7 OUT (out)

## LS204MN
designator U?
High-Performance Dual Operational Amplifier
footprint DIP8 (DIP; 8 Leads; Row Spacing 7.62 mm; Pitch 2.54 mm)
3D model DIP8 (DIP; 8 Leads; Row Spacing 7.62 mm; Pitch 2.54 mm)
pins on every part: 4 V- (power), 8 V+ (power)
part A pins: 1 OUT (out), 2 IN- (in), 3 IN+ (in)
part B pins: 5 IN+ (in), 6 IN- (in), 7 OUT (out)

## LS404CD
designator U?
High-Performance Quad Operational Amplifier
footprint SO14_N (SOIC, 14-Leads, Body 8.7x3.9mm, Pitch 1.27mm, IPC Medium Density)
footprint SO14_L (SOIC, 14-Leads, Body 8.7x3.9mm, Pitch 1.27mm, IPC High Density)
footprint SO14_M (SOIC, 14-Leads, Body 8.7x3.9mm, Pitch 1.27mm, IPC Low Density)
3D model SO14 (14-Pin Small Outline Integrated Circuit 1.27 mm Pitch)
pins on every part: 4 V+ (power), 11 V- (power)
part A pins: 1 OUT (out), 2 IN- (in), 3 IN+ (in)
part B pins: 5 IN+ (in), 6 IN- (in), 7 OUT (out)
part C pins: 8 OUT (out), 9 IN- (in), 10 IN+ (in)
part D pins: 12 IN+ (in), 13 IN- (in), 14 OUT (out)

## LS404CN
designator U?
High-Performance Quad Operational Amplifier
footprint DIP14 (DIP; 14 Leads; Row Spacing 7.62 mm; Pitch 2.54 mm)
3D model DIP14 (DIP; 14 Leads; Row Spacing 7.62 mm; Pitch 2.54 mm)
pins on every part: 4 V+ (power), 11 V- (power)
part A pins: 1 OUT (out), 2 IN- (in), 3 IN+ (in)
part B pins: 5 IN+ (in), 6 IN- (in), 7 OUT (out)
part C pins: 8 OUT (out), 9 IN- (in), 10 IN+ (in)
part D pins: 12 IN+ (in), 13 IN- (in), 14 OUT (out)

## LS404ID
designator U?
High-Performance Quad Operational Amplifier
footprint SO14_N (SOIC, 14-Leads, Body 8.7x3.9mm, Pitch 1.27mm, IPC Medium Density)
footprint SO14_L (SOIC, 14-Leads, Body 8.7x3.9mm, Pitch 1.27mm, IPC High Density)
footprint SO14_M (SOIC, 14-Leads, Body 8.7x3.9mm, Pitch 1.27mm, IPC Low Density)
3D model SO14 (14-Pin Small Outline Integrated Circuit 1.27 mm Pitch)
pins on every part: 4 V+ (power), 11 V- (power)
part A pins: 1 OUT (out), 2 IN- (in), 3 IN+ (in)
part B pins: 5 IN+ (in), 6 IN- (in), 7 OUT (out)
part C pins: 8 OUT (out), 9 IN- (in), 10 IN+ (in)
part D pins: 12 IN+ (in), 13 IN- (in), 14 OUT (out)

## LS404IN
designator U?
High-Performance Quad Operational Amplifier
footprint DIP14 (DIP; 14 Leads; Row Spacing 7.62 mm; Pitch 2.54 mm)
3D model DIP14 (DIP; 14 Leads; Row Spacing 7.62 mm; Pitch 2.54 mm)
pins on every part: 4 V+ (power), 11 V- (power)
part A pins: 1 OUT (out), 2 IN- (in), 3 IN+ (in)
part B pins: 5 IN+ (in), 6 IN- (in), 7 OUT (out)
part C pins: 8 OUT (out), 9 IN- (in), 10 IN+ (in)
part D pins: 12 IN+ (in), 13 IN- (in), 14 OUT (out)

## LS404MD
designator U?
High-Performance Quad Operational Amplifier
footprint SO14_N (SOIC, 14-Leads, Body 8.7x3.9mm, Pitch 1.27mm, IPC Medium Density)
footprint SO14_L (SOIC, 14-Leads, Body 8.7x3.9mm, Pitch 1.27mm, IPC High Density)
footprint SO14_M (SOIC, 14-Leads, Body 8.7x3.9mm, Pitch 1.27mm, IPC Low Density)
3D model SO14 (14-Pin Small Outline Integrated Circuit 1.27 mm Pitch)
pins on every part: 4 V+ (power), 11 V- (power)
part A pins: 1 OUT (out), 2 IN- (in), 3 IN+ (in)
part B pins: 5 IN+ (in), 6 IN- (in), 7 OUT (out)
part C pins: 8 OUT (out), 9 IN- (in), 10 IN+ (in)
part D pins: 12 IN+ (in), 13 IN- (in), 14 OUT (out)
